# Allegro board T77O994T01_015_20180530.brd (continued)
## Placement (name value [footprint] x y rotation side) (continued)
R142  10Kohm  [C-0402B-U58O293T00]  113.33 42.16 90 bottom
R143  10Kohm  [R-0402S0]  116.99 33.4 90 bottom
R144  5.11Kohm  [R-0402S0]  111.31 53.2 90 bottom
R145  5.11Kohm  [R-0402S0]  110.77 51.05 180 bottom
R146  150ohm  [C-0402B-U58O293T00]  117.19 60.47 90 bottom
R147  5.11Kohm  [R-0402S0]  109.75 51.05 180 bottom
R148  10Kohm  [R-0402S0]  108.73 51.07 0 bottom
R149  75ohm  [C-0402B-U58O293T00]  118.91 57.91 90 bottom
R150  4.7Kohm  [R-0402S0]  94.28 18.92 180 top
R151  22ohm  [R-0402S0]  83.91 20.73 90 top
R152  22ohm  [R-0402S0]  83.86 18.16 90 top
R153  22ohm  [R-0402S0]  83.99 17.14 90 top
R154  1Kohm  [R-0402S0]  132.56 13.37 180 bottom
R155  1Kohm  [R-0402S0]  21.3 68.23 90 top
R156  1Kohm  [R-0402S0]  137.13 13.37 0 bottom
R157  10Kohm  [R-0402S0]  134.08 13.37 180 bottom
R158  10Kohm  [R-0402S0]  129.51 13.37 0 top
R159  10Kohm  [R-0402S0]  134.08 17.18 0 top
R160  7.5Kohm  [C-0402B-U58O293T00]  116.54 40.22 90 bottom
R161  10Kohm  [R-0402S0]  132.56 13.37 0 top
R162  10Kohm  [R-0402S0]  131.03 17.18 0 top
R163  10Kohm  [R-0402S0]  132.56 17.18 0 top
R164  10Kohm  [R-0402S0]  131.03 13.37 0 top
R165  10Kohm  [R-0402S0]  129.51 17.18 0 top
R166  5.11Kohm  [R-0402S0]  120.79 69.87 0 top
R167  8.2Kohm  [R-0402S0]  114.19 32 0 bottom
R168  10Kohm  [R-0402S0]  107.97 68.34 0 top
R169  49.9ohm  [C-0402B-U58O293T00]  116.33 56.59 180 bottom
R170  49.9ohm  [R-0402S0]  150.82 63.6 90 top
R171  49.9ohm  [R-0402S0]  150.82 62.63 90 top
R172  121ohm  [R-0402S0]  145.72 68.45 180 top
R173  40.2ohm  [R-0402S0]  144.7 68.45 180 top
R174  51ohm  [R-0402S0]  110.58 69.88 180 top
R175  51ohm  [R-0402S0]  116.2 64.3 90 bottom
R176  130ohm  [R-0402S0]  143.68 68.45 180 top
R177  10Kohm  [R-0402S0]  67.16 43.55 0 top
R178  51ohm  [R-0402S0]  112.62 69.88 0 top
R179  51ohm  [R-0402S0]  114.7 63.49 0 bottom
R180  10Kohm  [C-0402B-U58O293T00]  118.43 61.84 135 bottom
R181  10Kohm  [C-0402B-U58O293T00]  116.6 63.01 0 bottom
R182  7.5Kohm  [C-0402B-U58O293T00]  118.14 40.85 270 bottom
R183  33ohm  [R-0402S0]  184.28 3.06 270 top
R184  10Kohm  [C-0402B-U58O293T00]  127.6 34.29 180 bottom
R185  1Kohm  [R-0402S0]  135.6 13.37 180 top
R186  20ohm  [R-0402S0]  132.56 17.18 180 bottom
R187  20ohm  [R-0402S0]  138.65 13.37 0 top
R188  20ohm  [R-0402S0]  137.13 13.37 0 top
R189  1Kohm  [R-0402S0]  163.27 59.73 0 top
R190  2ohm  [R-0402S0]  153.65 65.55 270 top
R191  1Kohm  [R-0402S0]  163.27 61.38 0 top
R192  33ohm  [R-0402S0]  183.77 4.97 270 top
R193  150ohm  [R-0402S0]  63.86 28.59 0 top
R194  75ohm  [R-0402S0]  65 28.59 0 top
R195  75ohm  [R-0402S0]  66.14 28.59 0 top
R196  75ohm  [R-0402S0]  67.41 28.59 0 top
R197  49.9ohm  [R-0402S0]  38.23 67.58 270 bottom
R198  240ohm  [R-0402S0]  31.11 72.91 0 bottom
R199  10ohm  [R-0402S0]  32.26 72.91 180 bottom
R200  10Kohm  [R-0402S0]  83.34 28.69 90 top
R201  10Kohm  [R-0402S0]  83.34 30.98 90 top
R202  1Kohm  [R-0402S0]  83.34 29.83 90 top
R203  10Kohm  [R-0402S0]  27.24 67.96 90 top
R204  10Kohm  [R-0402S0]  36.93 28.08 0 top
R205  1Kohm  [R-0402S0]  111.71 72.43 0 top
R206  0ohm  [R-0402S0]  36.93 29.86 0 top
R207  10Kohm  [R-0402S0]  94.59 70.25 180 top
R208  33ohm  [R-0402S0]  87.1 70.37 270 top
R209  33ohm  [R-0402S0]  93.24 69.84 270 top
R210  10Kohm  [R-0402S0]  62.23 44.59 270 top
R211  0ohm  [R-0402S0]  62.33 45.86 90 top
R212  10Kohm  [R-0402S0]  37.48 44.69 180 top
R213  49.9ohm  [R-0402S0]  67.69 40.02 90 top
R214  4.7Kohm  [R-0402S0]  187.83 10.3 270 bottom
R215  33ohm  [R-0402S0]  171 4.05 90 bottom
R216  33ohm  [R-0402S0]  171 5.07 90 bottom
R217  33ohm  [R-0402S0]  171 7.1 90 bottom
R218  33ohm  [R-0402S0]  182.88 7.51 180 bottom
R219  0ohm  [R-0402S0]  66.29 12.34 180 top
R220  0ohm  [R-0402S0]  67.31 12.34 180 top
R221  33ohm  [R-0402S0]  183.77 7.76 270 top
R222  1Kohm  [R-0402S0]  168.02 2.84 90 top
R223  0ohm  [R-0402S0]  167.39 11.07 90 bottom
R224  330ohm  [R-0402S0]  187.83 11.32 90 bottom
R225  4.7Kohm  [R-0402S0]  167.36 7.74 90 top
R226  330ohm  [R-0402S0]  167.36 6.72 270 top
R227  4.7Kohm  [R-0402S0]  155.54 5.62 180 bottom
R228  4.7Kohm  [R-0402S0]  167.36 4.41 90 top
R229  0ohm  [R-0402S0]  189.71 79.77 270 bottom
R230  0ohm  [R-0402S0]  189.59 84.72 270 bottom
R231  0ohm  [R-0402S0]  188.56 61.48 90 top
R232  0ohm  [R-0402S0]  189.71 80.79 90 bottom
R233  0ohm  [R-0402S0]  189.59 85.74 90 bottom
R234  0ohm  [R-0402S0]  188.56 60.47 270 top
R235  0ohm  [R-0402S0]  160.76 82.69 270 top
R236  0ohm  [R-0402S0]  160.76 81.8 270 top
R237  0ohm  [R-0402S0]  160.73 83.6 270 top
R238  0ohm  [R-0402S0]  163.04 84.09 90 top
R239  0ohm  [R-0402S0]  163.04 82.31 90 top
R240  10Kohm  [R-0402S0]  129.51 8.03 180 bottom
R241  10Kohm  [R-0402S0]  138.65 17.18 180 bottom
R242  1Kohm  [R-0402S0]  119.73 18.07 180 bottom
R243  10Kohm  [R-0402S0]  135.6 8.03 180 bottom
R244  1Kohm  [R-0402S0]  129.51 8.03 180 top
R245  1Kohm  [R-0402S0]  138.65 17.18 180 top
R246  10Kohm  [R-0402S0]  119.73 18.07 180 top
R247  1Kohm  [R-0402S0]  135.6 8.03 180 top
R248  1Kohm  [R-0402S0]  137.13 17.18 180 bottom
R249  1Kohm  [R-0402S0]  135.6 17.18 180 bottom
R250  10Kohm  [R-0402S0]  129.51 17.18 180 bottom
R251  5.11Kohm  [R-0402S0]  117.75 69.87 180 top
R252  5.11Kohm  [R-0402S0]  113.25 74.46 180 top
R253  10Kohm  [R-0402S0]  137.13 17.18 0 top
R254  10Kohm  [R-0402S0]  135.6 17.18 180 top
R255  1Kohm  [R-0402S0]  129.51 13.37 0 bottom
R256  5.11Kohm  [R-0402S0]  117.75 72.15 0 top
R257  5.11Kohm  [R-0402S0]  110.7 72.43 0 top
R258  5.11Kohm  [R-0402S0]  100.6 60.21 90 bottom
R259  5.11Kohm  [R-0402S0]  116.73 69.87 180 top
R260  5.11Kohm  [R-0402S0]  119.78 69.87 180 top
R261  5.11Kohm  [C-0402B-U58O293T00]  120.21 57.47 180 bottom
R262  5.11Kohm  [C-0402B-U58O293T00]  121.33 57.47 180 bottom
R263  5.11Kohm  [R-0402S0]  100.6 60.21 90 top
R264  5.11Kohm  [R-0402S0]  116.73 72.15 0 top
R265  5.11Kohm  [R-0402S0]  120.65 72.15 0 top
R266  5.11Kohm  [C-0402B-U58O293T00]  120.41 59.31 180 bottom
R267  5.11Kohm  [C-0402B-U58O293T00]  122.6 57.4 90 bottom
R268  5.11Kohm  [C-0402B-U58O293T00]  120.06 63.32 90 bottom
R269  5.11Kohm  [R-0402S0]  119.71 69.89 0 bottom
R270  5.11Kohm  [R-0402S0]  115.71 69.87 180 top
R271  5.11Kohm  [R-0402S0]  121.89 27.08 0 bottom
R272  5.11Kohm  [R-0402S0]  100.6 63.26 90 top
R273  330Kohm  [R-0402S0]  122.9 27.08 0 bottom
R274  5.11Kohm  [C-0402B-U58O293T00]  121.22 62.45 90 bottom
R275  5.11Kohm  [R-0402S0]  118.82 69.89 180 bottom
R276  5.11Kohm  [R-0402S0]  115.71 72.15 0 top
R277  5.11Kohm  [R-0402S0]  98.95 63.26 90 top
R278  5.11Kohm  [R-0402S0]  112.92 63.49 90 bottom
R279  5.11Kohm  [R-0402S0]  100.6 61.23 90 bottom
R280  240ohm  [R-0402S0]  114.82 72.15 0 top
R281  240ohm  [R-0402S0]  114.82 74.44 180 top
R282  240ohm  [C-0402B-U58O293T00]  125.11 62.58 90 bottom
R283  5.11Kohm  [R-0402S0]  112.92 62.61 270 bottom
R284  5.11Kohm  [R-0402S0]  100.6 61.23 90 top
R285  240ohm  [R-0402S0]  114.78 72.17 0 bottom
R286  240ohm  [R-0402S0]  115.71 74.44 0 top
R287  240ohm  [R-0402S0]  124.76 56.71 180 bottom
R288  5.11Kohm  [R-0402S0]  93.22 70.83 90 top
R289  10Kohm  [R-0402S0]  138.65 8.03 0 top
R290  5.11Kohm  [R-0402S0]  100.6 62.12 90 top
R291  240ohm  [C-0402B-U58O293T00]  118.39 59.48 45 bottom
R292  240ohm  [R-0402S0]  123.87 56.72 0 bottom
R293  5.11Kohm  [R-0402S0]  93.98 72.79 90 top
R294  1Kohm  [R-0402S0]  138.65 8.03 0 bottom
R295  5.11Kohm  [R-0402S0]  98.95 62.12 90 top
R296  1Kohm  [R-0402S0]  134.08 8.03 180 bottom
R297  10Kohm  [R-0402S0]  140.18 13.37 180 bottom
R298  1Kohm  [R-0402S0]  135.6 3.72 180 bottom
R299  10Kohm  [R-0402S0]  126.46 13.37 180 bottom
R300  1Kohm  [R-0402S0]  134.08 8.03 180 top
R301  1Kohm  [R-0402S0]  140.18 13.37 180 top
R302  10Kohm  [R-0402S0]  135.6 3.72 180 top
R303  1Kohm  [R-0402S0]  126.46 17.18 0 bottom
R304  4.7Kohm  [R-0402S0]  155.54 3.84 0 bottom
R305  0ohm  [R-0402S0]  183.77 9.54 270 top
R306  10Kohm  [R-0402S0]  33.27 18.69 0 bottom
R307  10Kohm  [R-0402S0]  34.29 18.69 0 bottom
R308  0ohm  [R-0402S0]  22.99 20.84 0 bottom
R309  0ohm  [R-0603S0]  84.07 18.81 180 bottom
R310  0ohm  [R-0402S0]  186.31 11.07 180 top
R311  0ohm  [R-0402S0]  119.18 72.71 90 top
R312  0ohm  [R-0402S0]  196.09 12.69 270 top
R313  10Kohm  [R-0402S0]  36.45 18.69 0 bottom
R314  0ohm  [R-0402S0]  194.44 13.1 180 top
R315  4.7Kohm  [R-0402S0]  33.5 47.15 90 top
R316  4.7Kohm  [R-0402S0]  194.51 7.76 90 bottom
R317  0ohm  [R-0402S0]  28.54 53.5 180 top
R318  0ohm  [R-0402S0]  27.53 53.5 180 top
R319  330ohm  [R-0402S0]  28.8 47.02 180 top
R320  330ohm  [R-0402S0]  35.27 50.96 0 top
R321  330ohm  [R-0402S0]  35.28 49.29 0 top
R322  4.7Kohm  [R-0402S0]  70.48 70.5 0 top
R323  0ohm  [R-0402S0]  63.35 76.85 270 top
R324  0ohm  [R-0402S0]  63.35 78.12 270 top
R325  0ohm  [R-0402S0]  47.44 55.64 0 top
R326  4.7Kohm  [R-0402S0]  50.89 55.28 270 top
R327  4.7Kohm  [R-0402S0]  50.83 56.28 270 top
R328  0ohm  [R-0402S0]  41.16 61.14 90 bottom
R329  0ohm  [R-0402S0]  41.12 62.14 90 bottom
R330  0ohm  [R-0402S0]  50.86 57.42 90 top
R331  4.7Kohm  [R-0402S0]  53.48 59.87 270 bottom
R332  4.7Kohm  [R-0402S0]  48.61 61.32 90 top
R333  4.7Kohm  [R-0402S0]  50.69 61.99 270 top
R334  4.7Kohm  [R-0402S0]  53.43 61.88 270 bottom
R335  4.7Kohm  [R-0402S0]  42.82 59.11 90 bottom
R336  4.7Kohm  [R-0402S0]  53.43 62.9 90 bottom
R337  4.7Kohm  [R-0402S0]  42.82 60.13 270 bottom
R338  10Kohm  [R-0402S0]  31.73 23.89 0 bottom
R339  10Kohm  [R-0402S0]  44.32 24.02 0 bottom
R340  10Kohm  [R-0402S0]  41.61 24.35 270 bottom
R341  4.7Kohm  [R-0402S0]  75.91 38.64 0 bottom
R342  10Kohm  [R-0402S0]  41.62 23.27 90 bottom
R343  1Kohm  [R-0402S0]  76.55 40.42 0 bottom
R344  0ohm  [R-0402S0]  37.31 48.29 270 top
R345  0ohm  [R-0402S0]  62.08 40.91 90 top
R346  0ohm  [R-0402S0]  62.08 41.93 90 top
R347  0ohm  [R-0402S0]  62.59 48.4 90 top
R348  10Kohm  [R-0402S0]  66.67 18.94 0 bottom
R349  10Kohm  [R-0402S0]  67.82 18.94 0 bottom
R350  4.7Kohm  [R-0402S0]  194.51 6.75 270 bottom
R351  10Kohm  [R-0402S0]  183.36 10.94 180 top
R352  10Kohm  [R-0402S0]  185.29 11.07 0 top
R353  0ohm  [R-0402S0]  49.76 53.1 0 top
R354  0ohm  [R-0402S0]  50.78 53.1 0 top
R355  0ohm  [R-0402S0]  48.74 53.1 0 top
R356  0ohm  [R-0402S0]  47.73 53.1 0 top
R357  0ohm  [R-0402S0]  46.71 53.1 0 top
R358  0ohm  [R-0402S0]  44.68 53.1 0 top
R359  2.2ohm  [R-0402S0]  194.18 13.48 0 bottom
R360  10Kohm  [R-0402S0]  37.31 49.29 270 top
R361  4.7Kohm  [R-0402S0]  35.66 38.37 90 top
R362  330ohm  [R-0402S0]  37.31 50.31 90 top
R363  33ohm  [R-0402S0]  35.66 39.39 270 top
R364  0ohm  [R-0402S0]  50.13 39.28 0 bottom
R365  0ohm  [R-0402S0]  48.66 41.28 270 bottom
R366  4.7Kohm  [R-0402S0]  26.8 18.56 90 bottom
R367  4.7Kohm  [R-0402S0]  28.19 21.73 0 bottom
R368  4.7Kohm  [R-0402S0]  20.57 12.84 0 top
R369  1Kohm  [R-0402S0]  19.56 12.84 180 top
R370  0ohm  [R-0402S0]  53.17 34.71 270 bottom
R371  0ohm  [R-0402S0]  37.31 38.37 90 top
R372  0ohm  [R-0402S0]  52.55 29.5 180 top
R373  0ohm  [R-0402S0]  54.05 38.39 90 bottom
R374  0ohm  [R-0402S0]  35.66 41.54 90 top
R375  0ohm  [R-0402S0]  59.9 34.96 0 bottom
R376  0ohm  [R-0402S0]  35.66 40.4 90 top
R377  0ohm  [R-0402S0]  43.39 33.18 0 bottom
R378  0ohm  [R-0402S0]  61.95 36.59 270 top
R379  0ohm  [R-0402S0]  56.87 29.48 180 top
R380  150ohm  [R-0402S0]  58.9 58.96 0 top
R381  150ohm  [R-0402S0]  57.5 58.96 0 top
R382  150ohm  [R-0402S0]  55.98 58.94 0 top
R383  150ohm  [R-0402S0]  54.99 58.94 0 top
R384  4.7Kohm  [R-0402S0]  42.77 57.67 90 top
R385  10Kohm  [R-0402S0]  42.77 56.66 90 top
R386  4.7Kohm  [R-0402S0]  36.32 57.55 270 top
R387  0ohm  [R-0402S0]  42.77 58.69 270 top
R388  10Kohm  [R-0402S0]  69.52 80.08 90 bottom
R389  0ohm  [R-0402S0]  69.56 65.69 90 bottom
R390  1Kohm  [R-0402S0]  53.31 74.46 90 bottom
R391  0ohm  [R-0402S0]  69.52 81.09 90 bottom
R392  2.2Kohm  [R-0402S0]  69.56 70.14 270 bottom
R393  2.2Kohm  [R-0402S0]  69.52 82.11 270 bottom
R394  2.2Kohm  [R-0402S0]  69.56 83.73 270 bottom
R395  4.7Kohm  [R-0402S0]  183.77 6.75 90 top
R396  10Kohm  [R-0402S0]  126.46 13.37 180 top
R397  1Kohm  [R-0402S0]  4.03 69.76 90 bottom
R398  1Kohm  [R-0402S0]  19.62 67.07 90 top
R399  0ohm  [R-0402S0]  11.65 70.52 180 bottom
R400  0ohm  [R-0402S0]  5.85 67.71 270 bottom
R401  150ohm  [R-0402S0]  19.63 63.4 90 top
R402  0ohm  [R-0402S0]  25.11 67.98 90 top
R403  51ohm  [R-0402S0]  5.85 70.88 90 bottom
R404  0ohm  [R-0402S0]  38.19 66.2 90 bottom
R405  1Kohm  [R-0402S0]  19.65 60.49 90 top
R406  1Kohm  [R-0402S0]  5.85 68.72 90 bottom
R407  0ohm  [R-0402S0]  21.3 67.2 90 top
R408  0ohm  [R-0402S0]  4.03 70.9 90 bottom
R409  0ohm  [R-0402S0]  19.62 68.21 90 top
R410  0ohm  [R-0402S0]  6.9 72.79 90 bottom
R411  0ohm  [R-0402S0]  24.13 67.1 90 top
R412  51ohm  [R-0402S0]  11.31 63.9 270 bottom
R413  51ohm  [R-0402S0]  11.31 64.91 270 bottom
R414  10Kohm  [R-0402S0]  11.31 65.93 270 bottom
R415  10Kohm  [R-0402S0]  11.31 66.94 270 bottom
R416  51ohm  [R-0402S0]  11.31 67.96 270 bottom
R417  51ohm  [R-0402S0]  11.31 68.98 270 bottom
R418  10Kohm  [R-0402S0]  11.31 62.88 270 bottom
R419  51ohm  [R-0402S0]  11.31 61.86 270 bottom
R420  953ohm  [R-0402S0]  4.54 71.92 90 bottom
R421  33ohm  [R-0402S0]  159.38 10.43 90 top
R422  33ohm  [R-0402S0]  161.04 10.43 90 top
R423  4.7Kohm  [R-0402S0]  60.71 45.99 90 bottom
R424  4.7Kohm  [R-0402S0]  60.71 47.01 90 bottom
R425  4.7Kohm  [R-0402S0]  58.29 42.43 90 bottom
R426  4.7Kohm  [R-0402S0]  58.29 43.32 90 bottom
R427  4.7Kohm  [R-0402S0]  50.29 47.13 270 bottom
R428  4.7Kohm  [R-0402S0]  50.29 46.12 270 bottom
R429  4.7Kohm  [R-0402S0]  54.86 40.53 0 bottom
R430  4.7Kohm  [R-0402S0]  53.98 40.53 0 bottom
R431  4.7Kohm  [R-0402S0]  41.78 44.21 0 bottom
R432  4.7Kohm  [R-0402S0]  42.8 44.21 0 bottom
R433  4.7Kohm  [R-0402S0]  45.97 40.15 0 bottom
R434  4.7Kohm  [R-0402S0]  44.96 40.15 0 bottom
R435  4.7Kohm  [R-0402S0]  42.93 40.53 0 bottom
R436  4.7Kohm  [R-0402S0]  43.94 40.53 0 bottom
R437  10Kohm  [R-0402S0]  43.66 53.1 0 top
R438  10Kohm  [R-0402S0]  45.7 53.1 0 top
R439  10Kohm  [R-0402S0]  138.65 3.72 0 top
R440  10Kohm  [R-0402S0]  129.51 3.72 0 top
R441  10Kohm  [R-0402S0]  131.03 8.03 0 top
R442  10Kohm  [R-0402S0]  137.13 8.03 0 top
R443  33ohm  [R-0402S0]  167.39 5.45 90 top
R444  4.7Kohm  [R-0402S0]  37.34 52.21 90 top
R445  4.7Kohm  [R-0402S0]  35.31 47.64 0 top
R446  330ohm  [R-0402S0]  30.73 47.26 180 top
R447  0ohm  [R-0402S0]  25.65 20.59 90 bottom
R448  49.9ohm  [R-0402S0]  135.6 13.37 180 bottom
R449  0ohm  [R-0402S0]  163.04 85.11 90 top
R450  10Kohm  [R-0402S0]  48.78 55.01 180 top
R451  33ohm  [R-0402S0]  93.55 26.07 90 bottom
R452  33ohm  [R-0402S0]  93.55 27.09 90 bottom
R453  10ohm  [R-0402S0]  83.19 28.59 270 bottom
R454  10ohm  [R-0402S0]  83.19 29.61 270 bottom
R455  10ohm  [R-0402S0]  83.19 30.62 270 bottom
R456  10ohm  [R-0402S0]  83.19 31.64 270 bottom
R457  20ohm  [R-0402S0]  72.52 29.35 270 bottom
R458  20ohm  [R-0402S0]  76.2 24.78 0 bottom
R459  0ohm  [R-0402S0]  42.8 59.71 270 top
R460  1Kohm  [R-0402S0]  55.12 24.65 270 bottom
R461  0ohm  [R-0402S0]  58.04 21.23 90 bottom
R462  0ohm  [R-0402S0]  134.62 21.73 180 bottom
R463  0ohm  [R-0402S0]  127.34 23.98 180 bottom
R464  0ohm  [R-0402S0]  134.08 13.37 180 top
R465  0ohm  [R-0402S0]  77.85 41.55 270 bottom
R466  0ohm  [R-0402S0]  21.95 12.84 0 top
R467  0ohm  [R-0402S0]  23.09 12.84 0 top
R468  10Kohm  [R-0402S0]  108.33 74.69 0 top
R469  10Kohm  [R-0402S0]  109.35 74.69 0 top
TP1  TP  [ICT020]  126.39 28.7 180 bottom
TP3  TP  [ICT020]  129.68 25.67 180 bottom
TP4  TP  [ICT]  192.15 5.99 0 bottom
TP5  TP  [ICT020]  133.49 24.4 180 bottom
TP6  TP  [ICT020]  131.67 22.64 180 bottom
TP7  TP  [ICT020]  129.68 23.13 180 bottom
TP8  TP  [ICT020]  133.49 26.94 180 bottom
TP9  TP  [ICT020]  38.1 57.29 180 bottom
TP10  TP  [ICT020]  55.21 67.34 180 bottom
TP11  TP  [ICT020]  11.91 75.85 270 bottom
TP12  TP  [ICT020]  70.23 49.42 0 top
U1  BDX_DE  [EBGA-78X78-1667-U58O259T00]  126.01 46.27 0 top
U2  74AVCH1T45GW  [SOT-363S0]  83.16 64.66 180 top
U3  W25Q32JVSSIQ  [SO-8G]  75.58 65.4 0 bottom
U4  74AVCH4T245PW  [SSOP-16C]  75.06 65.7 180 top
U5  TXB0302DQMR  [ULGA-1_8X1_2-8]  90.32 26.48 180 bottom
U7  PCA9617ADP  [MSOP-8]  141.24 85.87 270 top
U8  74AVCH4T245PW  [SSOP-16C]  77.8 29.17 180 bottom
U9  CY2304NZZXC-1T  [MSOP-8A]  89.2 18.79 0 top
U10  74AVCH4T245PW  [SSOP-16C]  66.51 33.89 90 top
U11  74AVCH4T245PW  [SSOP-16C]  32.74 67.45 180 bottom
U12  74LVC1G07SE-7  [SC-70-5A]  72.16 28.44 90 top
U13  74AVCH4T245PW  [SSOP-16C]  77.8 29.19 180 top
U14  74AVCH4T245PW  [SSOP-16C]  32.78 67.44 180 top
U15  74AVCH4T245PW  [SSOP-16C]  31.83 29.85 180 top
U16  74AVCH1T45GW  [SOT-363S0]  89.89 70.88 180 top
U17  74LVC1G07SE-7  [SC-70-5A]  64.87 43.96 0 top
U18  74LVC1G07SE-7  [SC-70-5A]  35.21 45.12 0 top
U19  74LVC1G07SE-7  [SC-70-5A]  64.87 40.91 180 top
U20  SN74CB3Q3244PWR  [SSOP-20]  177.04 6.49 180 bottom
U21  NC7SB3157P6X  [UM-6BH1_1]  184.51 10.96 180 bottom
U22  NC7SB3157P6X  [UM-6BH1_1]  170.13 10 0 bottom
U23  MX25L12835FM2I-10G  [SO-8G]  161.29 6.13 0 top
U24  MX25L12835FM2I-10G  [SO-8G]  161.29 6.24 180 bottom
U25  SLB 9670XQ2.0 FW7.63  [TQFN-5X5-32NSH]  188.72 6.11 90 top
U26  M24128-BRDW6TP  [MSOP-8A]  30.32 50.22 0 top
U27  TMP75AIDR  [SO-8H1_75]  66.01 71.53 180 top
U28  74LVC1G07SE-7  [SC-70-5A]  48.24 59.07 90 top
U29  74LVC1G07SE-7  [SC-70-5A]  51.11 59.71 90 top
U30  PCA9539PW  [SSOP-24C]  48.15 58.6 0 bottom
U31  EPM1270F256I5N  [PBGA-16X16-256B-H2_2]  50.14 41.29 180 top
U32  74AVCH1T45GW  [SOT-363S0]  197.61 13.22 180 bottom
U33  74LVC1G08GW  [SOT-353-H1_1S0]  55.09 26.45 270 top
U34  TPS3808G33DBVR  [SOT-23-6]  39.55 57.61 0 top
U35  74AVCH2T45DC  [TSSOP-8S2]  45.47 27.96 90 top
U36  TMP235A2DCKR  [SC-70-5A]  110.87 44.72 270 bottom
Y1  25MHz  [O-S3_2X2_5-4F]  101.37 56.64 0 top
Y2  32.768KHz  [O-3_2X1_5-2A]  122.81 18.81 90 top
Y3  25MHz  [O-3_2X2_5-4GS0]  112.04 18.03 90 top
Y4  25MHz  [O-3_2X2_5-4JS0]  31.98 38.24 0 top

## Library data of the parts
BAT1 = BB3320E
C1-C8 = CAP: signal model: CAP_C-0402S0_220NF_220nF
C9-C16 = CAP: signal model: CAP_C-0402S0_100NF_100nF
C17-C104 C107 C108 C114 C116-C141 C144-C148 C151-C183 C185-C193 C198-C200 C205-C210 C3812 C3813 PC2-PC5 PC7 PC11-PC15 PC18-PC21 PC24-PC41 PC44-PC48 PC52 PC67 PC68 PC70-PC72 PC75 PC77-PC84 PC111-PC115 PC137 PC139 PC140 PC142 PC144 PC146-PC148 PC151 PC162 PC163 PC165-PC168 PC170-PC172 PC174-PC178 PC180 PC182-PC184 PC186-PC196 PC199-PC206 PC208 PC209 PC211-PC220 PC222-PC231 PC233-PC236 PC238-PC241 PC243 PC244 PC246-PC250 PC252 PC255 PC262 PC264-PC267 PC270-PC275 PC295-PC307 PC309 PC312 PC313 PC316 PC318 PC322 PC325-PC336 PC338-PC340 PC347-PC349 = CAP
C201-C204 = CAP: signal model: CAP_C-0402S0_10NF_10nF
CN1 CN2 = DDR4 ECC SODIMM CONN_2
D1 D3-D6 = LED
D2 D7 D8 = BAT54CLT1
H1 MHS1-MHS4 = TOOLING HOLE-1PIN-MPTH
J1 = CON7X2
J2 = CON4X1
J3 = CON4X1_0
J6 = CON4X2
J8 = CON5X2
J9 = AS0BC23-S67BM-LH_0
J10 = PCIE CONN_0
J11 = CON2X2
J12 = CON30X2
L1 PJ20-PJ22 PR7-PR26 PR31-PR38 PR42 PR57 PR73 PR79 PR80 PR107-PR112 PR114-PR207 PR209 PR210 PR217 PR235 PR242-PR252 PR254 PR259-PR261 PR263 PR265-PR269 PR271-PR282 PR284-PR287 PR289-PR305 R1-R21 R29-R469 = RES
L2 L3 L7 PL1 PL2 PL8-PL16 = INDUCTOR
M1-M4 = Hole-MTG-8VIA
PC1 PC6 PC16 PC17 PC258 PC259 = CAP_0
PC8-PC10 PC22 PC23 PC69 PC257 PC263 = CAP_0: signal model: DEFAULT_CAPACITOR_2.2e+07pF_1_2
PC152 PC173 PC179 PC185 PC232 PC237 PC242 PC256 PC284 PC292 PC293 PC323 PC324 = CAP AL
PNTC2-PNTC8 = THERMISTOR
PR1 PR2 PR222 PR223 PR226 PR228 PR231 PR233 PR237 PR239 = RES_0
PR214-PR216 PR218 PR219 PR221 PR224 PR227 PR229 PR232 PR234 PR236 PR238 PR241 = RES_11
PU1 PU20 = TPS562219_563219
PU2 = TPS56628DDAR
PU5 PU6 = TPS74801DRCR
PU11 = TPS51200
PU14 = TPS54618RTER
PU17 = P_TPS51620RHAR_QFN40_1: room: PWR_VCORE
PU18 PU19 PU22 PU26 = CSD95373AQ5M
PU21 PU27 = TPS53623RSMR
PU24 = NCP45540IMNTWG-H
PU25 = NCP45520IMNTWG
Q1 Q4 Q5 = NFETX2-6P-SGD
Q2 Q3 Q6 = NPN-3P-BEC
TP1 TP3-TP12 = TP
U1 = BDX_DE_NEW
U2 U16 U32 = 74AVCH1T45GW
U3 = W25X40AVSNIG
U4 U8 U10 U11 U13-U15 = 74AVCH4T245PW
U5 = TXS0102DQER
U7 = PCA9617ADPJ
U9 = CY2304NZ
U12 U17-U19 U28 U29 = 74LVC1G34GW
U20 = QS3VH244PAG_0
U21 U22 = NC7SB3157P6X
U23 U24 = MX25L12835FM2I-10G
U25 = SLB 9670VQ2_4
U26 = AT24C02N
U27 = TMP75AIDR
U30 = PCA9539PW
U31 = EPM1270F256C5
U33 = 74LVC1G08
U34 = TPS3808G33DBVR
U35 = SN74AVC2T45DCUR_0
U36 = TPS71701DCKR_1
Y1 Y3 = XTAL-4
Y2 = XTAL
Y4 = OSC4PIN

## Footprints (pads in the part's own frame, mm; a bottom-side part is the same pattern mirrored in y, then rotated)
BA-D23_1X5_8-3S0
  round 1.575 hole 0.965: P1(5,-1.8) P3(-5,-1.8)
  round 1.549 hole 0.94: P2(0,1.8)
C-0402A
  custom 0.153x0.153 smd: 1(0,-0.459) 2(0,0.459)
C-0402B-U58O293T00
  custom 0.104x0.104 smd: 1(0,-0.4) 2(0,0.4)
C-0402S0
  custom 0.127x0.127 smd: 1(0,-0.406) 2(0,0.406)
C-0603S0
  custom 0.191x0.191 smd: 1(0,-0.686) 2(0,0.686)
C-0805
  custom 0.254x0.254 smd: 1(0,-0.889) 2(0,0.889)
C-0805-H1_35
  custom 0.254x0.254 smd: 1(0,-0.889) 2(0,0.889)
C-1206
  custom 0.362x0.362 smd: 1(0,-1.333) 2(0,1.333)
C-1210
  custom 0.381x0.381 smd: 1(0,-1.27) 2(0,1.27)
C-1210B-H2_8
  custom 0.381x0.381 smd: 1(0,-1.27) 2(0,1.27)
C-S7_3X4_3-2
  rect 2.896x2.083 smd: 1(0,-3.117) 2(0,3.117)
C-TAN-S7_3X4_3
  rect 2.997x2.007 smd: 1(0,3.003) 2(0,-3.003)
CN-D2X2-4_2RT
  round 2.997 hole 2.997 unplated: (0,-0.2)
  round 2.311 hole 1.702: 1(-2.1,-7.5) 2(2.1,-7.5) 3(-2.1,-13) 4(2.1,-13)
CN-EXPPCI-75G
  round 1.295 hole 1.295 unplated: (1.375,-10)
  round 1.753 hole 1.753 unplated: (1.375,10)
  rect 1.27x0.305 smd: 1(-4.348,-9.253) 3(-4.348,-8.753) 5(-4.348,-8.253) 7(-4.348,-7.753) 9(-4.348,-7.253) 11(-4.348,-6.753) 13(-4.348,-6.253) 15(-4.348,-5.753) 17(-4.348,-5.252) 19(-4.348,-4.752) 21(-4.348,-4.252) 23(-4.348,-3.752) 25(-4.348,-3.252) 27(-4.348,-2.752) 29(-4.348,-2.252) 31(-4.348,-1.752) 33(-4.348,-1.251) 35(-4.348,-0.751) 37(-4.348,-0.251) 39(-4.348,0.249) 41(-4.348,0.749) 43(-4.348,1.249) 45(-4.348,1.749) 47(-4.348,2.249) 49(-4.348,2.75) 51(-4.348,3.25) 53(-4.348,3.75) 55(-4.348,4.25) 57(-4.348,4.75) 67(-4.348,7.25) 69(-4.348,7.75) 71(-4.348,8.25) 73(-4.348,8.751) 75(-4.348,9.251)
  rect 1.219x0.305 smd: 2(4.123,-9.004) 4(4.123,-8.503) 6(4.123,-8.003) 8(4.123,-7.503) 10(4.123,-7.003) 12(4.123,-6.503) 14(4.123,-6.003) 16(4.123,-5.503) 18(4.123,-5.003) 20(4.123,-4.502) 22(4.123,-4.002) 24(4.123,-3.502) 26(4.123,-3.002) 28(4.123,-2.502) 30(4.123,-2.002) 32(4.123,-1.502) 34(4.123,-1.002) 36(4.123,-0.501) 38(4.123,-0.001) 40(4.123,0.499) 42(4.123,0.999) 44(4.123,1.499) 46(4.123,1.999) 48(4.123,2.499) 50(4.123,2.999) 52(4.123,3.5) 54(4.123,4) 56(4.123,4.5) 58(4.123,5) 68(4.123,7.5) 70(4.123,8) 72(4.123,8.5) 74(4.123,9)
  rect 3.15x1.575 smd: S1(-3.125,10.35) S2(-3.125,-10.35)
CN-EXPPCI-164FPCS0
  rect 3.2x0.711 smd: A1(-2.38,-41.5) B81(-2.38,40.5)
  rect 4.191x0.711 smd: A2(-2.875,-40.5) A3(-2.875,-39.5) A4(-2.875,-38.5) A5(-2.875,-37.5) A6(-2.875,-36.5) A7(-2.875,-35.5) A8(-2.875,-34.5) A9(-2.875,-33.5) A10(-2.875,-32.5) A11(-2.875,-31.5) A12(-2.875,-28.5) A13(-2.875,-27.5) A14(-2.875,-26.5) A15(-2.875,-25.5) A16(-2.875,-24.5) A17(-2.875,-23.5) A18(-2.875,-22.5) A19(-2.875,-21.5) A20(-2.875,-20.5) A21(-2.875,-19.5) A22(-2.875,-18.5) A23(-2.875,-17.5) A24(-2.875,-16.5) A25(-2.875,-15.5) A26(-2.875,-14.5) A27(-2.875,-13.5) A28(-2.875,-12.5) A29(-2.875,-11.5) A30(-2.875,-10.5) A31(-2.875,-9.5) A32(-2.875,-8.5) A33(-2.875,-7.5) A34(-2.875,-6.5) A35(-2.875,-5.5) A36(-2.875,-4.5) A37(-2.875,-3.5) A38(-2.875,-2.5) A39(-2.875,-1.5) A40(-2.875,-0.5) A41(-2.875,0.5) A42(-2.875,1.5) A43(-2.875,2.5) A44(-2.875,3.5) A45(-2.875,4.5) A46(-2.875,5.5) A47(-2.875,6.5) A48(-2.875,7.5) A49(-2.875,8.5) A50(-2.875,9.5) A51(-2.875,10.5) A52(-2.875,11.5) A53(-2.875,12.5) A54(-2.875,13.5) A55(-2.875,14.5) A56(-2.875,15.5) A57(-2.875,16.5) A58(-2.875,17.5) A59(-2.875,18.5) A60(-2.875,19.5) A61(-2.875,20.5) A62(-2.875,21.5) A63(-2.875,22.5) A64(-2.875,23.5) A65(-2.875,24.5) A66(-2.875,25.5) A67(-2.875,26.5) A68(-2.875,27.5) A69(-2.875,28.5) A70(-2.875,29.5) A71(-2.875,30.5) A72(-2.875,31.5) A73(-2.875,32.5) A74(-2.875,33.5) A75(-2.875,34.5) A76(-2.875,35.5) A77(-2.875,36.5) A78(-2.875,37.5) A79(-2.875,38.5) A80(-2.875,39.5) A81(-2.875,40.5) A82(-2.875,41.5) B1(-2.875,-41.5) B2(-2.875,-40.5) B3(-2.875,-39.5) B4(-2.875,-38.5) B5(-2.875,-37.5) B6(-2.875,-36.5) B7(-2.875,-35.5) B8(-2.875,-34.5) B9(-2.875,-33.5) B10(-2.875,-32.5) B11(-2.875,-31.5) B12(-2.875,-28.5) B13(-2.875,-27.5) B14(-2.875,-26.5) B15(-2.875,-25.5) B16(-2.875,-24.5) B17(-2.875,-23.5) B18(-2.875,-22.5) B19(-2.875,-21.5) B20(-2.875,-20.5) B21(-2.875,-19.5) B22(-2.875,-18.5) B23(-2.875,-17.5) B24(-2.875,-16.5) B25(-2.875,-15.5) B26(-2.875,-14.5) B27(-2.875,-13.5) B28(-2.875,-12.5) B29(-2.875,-11.5) B30(-2.875,-10.5) B31(-2.875,-9.5) B32(-2.875,-8.5) B33(-2.875,-7.5) B34(-2.875,-6.5) B35(-2.875,-5.5) B36(-2.875,-4.5) B37(-2.875,-3.5) B38(-2.875,-2.5) B39(-2.875,-1.5) B40(-2.875,-0.5) B41(-2.875,0.5) B42(-2.875,1.5) B43(-2.875,2.5) B44(-2.875,3.5) B45(-2.875,4.5) B46(-2.875,5.5) B47(-2.875,6.5) B48(-2.875,7.5) B49(-2.875,8.5) B50(-2.875,9.5) B51(-2.875,10.5) B52(-2.875,11.5) B53(-2.875,12.5) B54(-2.875,13.5) B55(-2.875,14.5) B56(-2.875,15.5) B57(-2.875,16.5) B58(-2.875,17.5) B59(-2.875,18.5) B60(-2.875,19.5) B61(-2.875,20.5) B62(-2.875,21.5) B63(-2.875,22.5) B64(-2.875,23.5) B65(-2.875,24.5) B66(-2.875,25.5) B67(-2.875,26.5) B68(-2.875,27.5) B69(-2.875,28.5) B70(-2.875,29.5) B71(-2.875,30.5) B72(-2.875,31.5) B73(-2.875,32.5) B74(-2.875,33.5) B75(-2.875,34.5) B76(-2.875,35.5) B77(-2.875,36.5) B78(-2.875,37.5) B79(-2.875,38.5) B80(-2.875,39.5) B82(-2.875,41.5)
CN-EXPPCI-260A-T77O759
  round 1.753 hole 1.753 unplated: (-34.4,0)
  round 1.194 hole 1.194 unplated: (34.4,0)
  rect 0.305x1.473 smd: 1(-33.383,-3.971) 2(-33.133,3.971) 3(-32.883,-3.971) 4(-32.633,3.971) 5(-32.383,-3.971) 6(-32.133,3.971) 7(-31.883,-3.971) 8(-31.633,3.971) 9(-31.383,-3.971) 10(-31.133,3.971) 11(-30.883,-3.971) 12(-30.633,3.971) 13(-30.383,-3.971) 14(-30.133,3.971) 15(-29.883,-3.971) 16(-29.632,3.971) 17(-29.382,-3.971) 18(-29.132,3.971) 19(-28.882,-3.971) 20(-28.632,3.971) 21(-28.382,-3.971) 22(-28.132,3.971) 23(-27.882,-3.971) 24(-27.632,3.971) 25(-27.382,-3.971) 26(-27.132,3.971) 27(-26.882,-3.971) 28(-26.632,3.971) 29(-26.382,-3.971) 30(-26.132,3.971) 31(-25.882,-3.971) 32(-25.631,3.971) 33(-25.381,-3.971) 34(-25.131,3.971) 35(-24.881,-3.971) 36(-24.631,3.971) 37(-24.381,-3.971) 38(-24.131,3.971) 39(-23.881,-3.971) 40(-23.631,3.971) 41(-23.381,-3.971) 42(-23.131,3.971) 43(-22.881,-3.971) 44(-22.631,3.971) 45(-22.381,-3.971) 46(-22.131,3.971) 47(-21.881,-3.971) 48(-21.63,3.971) 49(-21.38,-3.971) 50(-21.13,3.971) 51(-20.88,-3.971) 52(-20.63,3.971) 53(-20.38,-3.971) 54(-20.13,3.971) 55(-19.88,-3.971) 56(-19.63,3.971) 57(-19.38,-3.971) 58(-19.13,3.971) 59(-18.88,-3.971) 60(-18.63,3.971) 61(-18.38,-3.971) 62(-18.13,3.971) 63(-17.88,-3.971) 64(-17.629,3.971) 65(-17.379,-3.971) 66(-17.129,3.971) 67(-16.879,-3.971) 68(-16.629,3.971) 69(-16.379,-3.971) 70(-16.129,3.971) 71(-15.879,-3.971) 72(-15.629,3.971) 73(-15.379,-3.971) 74(-15.129,3.971) 75(-14.879,-3.971) 76(-14.629,3.971) 77(-14.379,-3.971) 78(-14.128,3.971) 79(-13.879,-3.971) 80(-13.628,3.971) 81(-13.378,-3.971) 82(-13.128,3.971) 83(-12.878,-3.971) 84(-12.628,3.971) 85(-12.378,-3.971) 86(-12.128,3.971) 87(-11.878,-3.971) 88(-11.628,3.971) 89(-11.378,-3.971) 90(-11.128,3.971) 91(-10.878,-3.971) 92(-10.628,3.971) 93(-10.378,-3.971) 94(-10.127,3.971) 95(-9.878,-3.971) 96(-9.627,3.971) 97(-9.377,-3.971) 98(-9.127,3.971) 99(-8.877,-3.971) 100(-8.627,3.971) 101(-8.377,-3.971) 102(-8.127,3.971) 103(-7.877,-3.971) 104(-7.627,3.971) 105(-7.377,-3.971) 106(-7.127,3.971) 107(-6.877,-3.971) 108(-6.627,3.971) 109(-6.377,-3.971) 110(-6.126,3.971) 111(-5.877,-3.971) 112(-5.626,3.971) 113(-5.376,-3.971) 114(-5.126,3.971) 115(-4.876,-3.971) 116(-4.626,3.971) 117(-4.376,-3.971) 118(-4.126,3.971) 119(-3.876,-3.971) 120(-3.626,3.971) 121(-3.376,-3.971) 122(-3.126,3.971) 123(-2.876,-3.971) 124(-2.626,3.971) 125(-2.376,-3.971) 126(-2.125,3.971) 127(-1.876,-3.971) 128(-1.625,3.971) 129(-1.375,-3.971) 130(-1.125,3.971) 131(-0.875,-3.971) 132(-0.625,3.971) 133(-0.375,-3.971) 134(-0.125,3.971) 135(0.125,-3.971) 136(0.375,3.971) 137(0.625,-3.971) 138(0.875,3.971) 139(1.125,-3.971) 140(1.375,3.971) 141(1.625,-3.971) 142(1.876,3.971) 143(2.125,-3.971) 144(2.376,3.971) 145(4.626,-3.971) 146(4.876,3.971) 147(5.126,-3.971) 148(5.376,3.971) 149(5.626,-3.971) 150(5.877,3.971) 151(6.126,-3.971) 152(6.377,3.971) 153(6.627,-3.971) 154(6.877,3.971) 155(7.127,-3.971) 156(7.377,3.971) 157(7.627,-3.971) 158(7.877,3.971) 159(8.127,-3.971) 160(8.377,3.971) 161(8.627,-3.971) 162(8.877,3.971) 163(9.127,-3.971) 164(9.377,3.971) 165(9.627,-3.971) 166(9.878,3.971) 167(10.127,-3.971) 168(10.378,3.971) 169(10.628,-3.971) 170(10.878,3.971) 171(11.128,-3.971) 172(11.378,3.971) 173(11.628,-3.971) 174(11.878,3.971) 175(12.128,-3.971) 176(12.378,3.971) 177(12.628,-3.971) 178(12.878,3.971) 179(13.128,-3.971) 180(13.378,3.971) 181(13.628,-3.971) 182(13.879,3.971) 183(14.128,-3.971) 184(14.379,3.971) 185(14.629,-3.971) 186(14.879,3.971) 187(15.129,-3.971) 188(15.379,3.971) 189(15.629,-3.971) 190(15.879,3.971) 191(16.129,-3.971) 192(16.379,3.971) 193(16.629,-3.971) 194(16.879,3.971) 195(17.129,-3.971) 196(17.379,3.971) 197(17.629,-3.971) 198(17.88,3.971) 199(18.13,-3.971) 200(18.38,3.971) 201(18.63,-3.971) 202(18.88,3.971) 203(19.13,-3.971) 204(19.38,3.971) 205(19.63,-3.971) 206(19.88,3.971) 207(20.13,-3.971) 208(20.38,3.971) 209(20.63,-3.971) 210(20.88,3.971) 211(21.13,-3.971) 212(21.38,3.971) 213(21.63,-3.971) 214(21.881,3.971) 215(22.131,-3.971) 216(22.381,3.971) 217(22.631,-3.971) 218(22.881,3.971) 219(23.131,-3.971) 220(23.381,3.971) 221(23.631,-3.971) 222(23.881,3.971) 223(24.131,-3.971) 224(24.381,3.971) 225(24.631,-3.971) 226(24.881,3.971) 227(25.131,-3.971) 228(25.381,3.971) 229(25.631,-3.971) 230(25.882,3.971) 231(26.132,-3.971) 232(26.382,3.971) 233(26.632,-3.971) 234(26.882,3.971) 235(27.132,-3.971) 236(27.382,3.971) 237(27.632,-3.971) 238(27.882,3.971) 239(28.132,-3.971) 240(28.382,3.971) 241(28.632,-3.971) 242(28.882,3.971) 243(29.132,-3.971) 244(29.382,3.971) 245(29.632,-3.971) 246(29.883,3.971) 247(30.133,-3.971) 248(30.383,3.971) 249(30.633,-3.971) 250(30.883,3.971) 251(31.133,-3.971) 252(31.383,3.971) 253(31.633,-3.971) 254(31.883,3.971) 255(32.133,-3.971) 256(32.383,3.971) 257(32.633,-3.971) 258(32.883,3.971) 259(33.133,-3.971) 260(33.383,3.971)
  rect 0.406x0.406 smd: S1(32.455,-11.874) S2(-32.455,-11.874)
CN-EXPPCI-260C
  round 1.753 hole 1.753 unplated: (-34.4,0)
  round 1.194 hole 1.194 unplated: (34.4,0)
  rect 0.305x1.473 smd: 1(-33.391,-3.871) 2(-33.141,3.871) 3(-32.891,-3.871) 4(-32.641,3.871) 5(-32.391,-3.871) 6(-32.141,3.871) 7(-31.891,-3.871) 8(-31.641,3.871) 9(-31.391,-3.871) 10(-31.141,3.871) 11(-30.891,-3.871) 12(-30.641,3.871) 13(-30.391,-3.871) 14(-30.14,3.871) 15(-29.89,-3.871) 16(-29.64,3.871) 17(-29.39,-3.871) 18(-29.14,3.871) 19(-28.89,-3.871) 20(-28.64,3.871) 21(-28.39,-3.871) 22(-28.14,3.871) 23(-27.89,-3.871) 24(-27.64,3.871) 25(-27.39,-3.871) 26(-27.14,3.871) 27(-26.89,-3.871) 28(-26.64,3.871) 29(-26.39,-3.871) 30(-26.139,3.871) 31(-25.889,-3.871) 32(-25.639,3.871) 33(-25.389,-3.871) 34(-25.139,3.871) 35(-24.889,-3.871) 36(-24.639,3.871) 37(-24.389,-3.871) 38(-24.139,3.871) 39(-23.889,-3.871) 40(-23.639,3.871) 41(-23.389,-3.871) 42(-23.139,3.871) 43(-22.889,-3.871) 44(-22.639,3.871) 45(-22.389,-3.871) 46(-22.138,3.871) 47(-21.888,-3.871) 48(-21.638,3.871) 49(-21.388,-3.871) 50(-21.138,3.871) 51(-20.888,-3.871) 52(-20.638,3.871) 53(-20.388,-3.871) 54(-20.138,3.871) 55(-19.888,-3.871) 56(-19.638,3.871) 57(-19.388,-3.871) 58(-19.138,3.871) 59(-18.888,-3.871) 60(-18.638,3.871) 61(-18.388,-3.871) 62(-18.137,3.871) 63(-17.887,-3.871) 64(-17.637,3.871) 65(-17.387,-3.871) 66(-17.137,3.871) 67(-16.887,-3.871) 68(-16.637,3.871) 69(-16.387,-3.871) 70(-16.137,3.871) 71(-15.887,-3.871) 72(-15.637,3.871) 73(-15.387,-3.871) 74(-15.137,3.871) 75(-14.887,-3.871) 76(-14.636,3.871) 77(-14.387,-3.871) 78(-14.136,3.871) 79(-13.886,-3.871) 80(-13.636,3.871) 81(-13.386,-3.871) 82(-13.136,3.871) 83(-12.886,-3.871) 84(-12.636,3.871) 85(-12.386,-3.871) 86(-12.136,3.871) 87(-11.886,-3.871) 88(-11.636,3.871) 89(-11.386,-3.871) 90(-11.136,3.871) 91(-10.886,-3.871) 92(-10.635,3.871) 93(-10.386,-3.871) 94(-10.135,3.871) 95(-9.885,-3.871) 96(-9.635,3.871) 97(-9.385,-3.871) 98(-9.135,3.871) 99(-8.885,-3.871) 100(-8.635,3.871) 101(-8.385,-3.871) 102(-8.135,3.871) 103(-7.885,-3.871) 104(-7.635,3.871) 105(-7.385,-3.871) 106(-7.135,3.871) 107(-6.885,-3.871) 108(-6.634,3.871) 109(-6.385,-3.871) 110(-6.134,3.871) 111(-5.884,-3.871) 112(-5.634,3.871) 113(-5.384,-3.871) 114(-5.134,3.871) 115(-4.884,-3.871) 116(-4.634,3.871) 117(-4.384,-3.871) 118(-4.134,3.871) 119(-3.884,-3.871) 120(-3.634,3.871) 121(-3.384,-3.871) 122(-3.134,3.871) 123(-2.884,-3.871) 124(-2.633,3.871) 125(-2.384,-3.871) 126(-2.133,3.871) 127(-1.883,-3.871) 128(-1.633,3.871) 129(-1.383,-3.871) 130(-1.133,3.871) 131(-0.883,-3.871) 132(-0.633,3.871) 133(-0.383,-3.871) 134(-0.133,3.871) 135(0.117,-3.871) 136(0.367,3.871) 137(0.617,-3.871) 138(0.867,3.871) 139(1.117,-3.871) 140(1.368,3.871) 141(1.617,-3.871) 142(1.868,3.871) 143(2.118,-3.871) 144(2.368,3.871) 145(4.618,-3.871) 146(4.868,3.871) 147(5.118,-3.871) 148(5.368,3.871) 149(5.618,-3.871) 150(5.868,3.871) 151(6.118,-3.871) 152(6.368,3.871) 153(6.618,-3.871) 154(6.868,3.871) 155(7.118,-3.871) 156(7.369,3.871) 157(7.618,-3.871) 158(7.869,3.871) 159(8.119,-3.871) 160(8.369,3.871) 161(8.619,-3.871) 162(8.869,3.871) 163(9.119,-3.871) 164(9.369,3.871) 165(9.619,-3.871) 166(9.869,3.871) 167(10.119,-3.871) 168(10.369,3.871) 169(10.619,-3.871) 170(10.869,3.871) 171(11.119,-3.871) 172(11.37,3.871) 173(11.619,-3.871) 174(11.87,3.871) 175(12.12,-3.871) 176(12.37,3.871) 177(12.62,-3.871) 178(12.87,3.871) 179(13.12,-3.871) 180(13.37,3.871) 181(13.62,-3.871) 182(13.87,3.871) 183(14.12,-3.871) 184(14.37,3.871) 185(14.62,-3.871) 186(14.87,3.871) 187(15.12,-3.871) 188(15.371,3.871) 189(15.62,-3.871) 190(15.871,3.871) 191(16.121,-3.871) 192(16.371,3.871) 193(16.621,-3.871) 194(16.871,3.871) 195(17.121,-3.871) 196(17.371,3.871) 197(17.621,-3.871) 198(17.871,3.871) 199(18.121,-3.871) 200(18.371,3.871) 201(18.621,-3.871) 202(18.871,3.871) 203(19.121,-3.871) 204(19.372,3.871) 205(19.622,-3.871) 206(19.872,3.871) 207(20.122,-3.871) 208(20.372,3.871) 209(20.622,-3.871) 210(20.872,3.871) 211(21.122,-3.871) 212(21.372,3.871) 213(21.622,-3.871) 214(21.872,3.871) 215(22.122,-3.871) 216(22.372,3.871) 217(22.622,-3.871) 218(22.872,3.871) 219(23.122,-3.871) 220(23.373,3.871) 221(23.623,-3.871) 222(23.873,3.871) 223(24.123,-3.871) 224(24.373,3.871) 225(24.623,-3.871) 226(24.873,3.871) 227(25.123,-3.871) 228(25.373,3.871) 229(25.623,-3.871) 230(25.873,3.871) 231(26.123,-3.871) 232(26.373,3.871) 233(26.623,-3.871) 234(26.873,3.871) 235(27.123,-3.871) 236(27.374,3.871) 237(27.624,-3.871) 238(27.874,3.871) 239(28.124,-3.871) 240(28.374,3.871) 241(28.624,-3.871) 242(28.874,3.871) 243(29.124,-3.871) 244(29.374,3.871) 245(29.624,-3.871) 246(29.874,3.871) 247(30.124,-3.871) 248(30.374,3.871) 249(30.624,-3.871) 250(30.874,3.871) 251(31.124,-3.871) 252(31.375,3.871) 253(31.625,-3.871) 254(31.875,3.871) 255(32.125,-3.871) 256(32.375,3.871) 257(32.625,-3.871) 258(32.875,3.871) 259(33.125,-3.871) 260(33.375,3.871)
  rect 2.413x3.912 smd: S1(-37.75,-8) S2(37.75,-12)
CN-S4X2-2_54HD
  rect 2.362x1.245 smd: 1(3.007,-3.81) 2(-3.007,-3.81) 3(3.007,-1.27) 4(-3.007,-1.27) 5(3.007,1.27) 6(-3.007,1.27) 7(3.007,3.81) 8(-3.007,3.81)
CN-S5X2-2_54AHDS0
  rect 2.362x1.245 smd: 1(3.007,-5.08) 2(-3.007,-5.08) 3(3.007,-2.54) 4(-3.007,-2.54) 5(3.007,0) 6(-3.007,0) 7(3.007,2.54) 8(-3.007,2.54) 9(3.007,5.08) 10(-3.007,5.08)
CN-S7X2-2HDS1
  round 1.143 hole 1.143 unplated: (0,5) (0,-5)
  rect 1.829x0.813 smd: 1(2.644,-6) 2(-2.644,-6) 3(2.644,-4) 4(-2.644,-4) 5(2.644,-2) 6(-2.644,-2) 7(2.644,0) 8(-2.644,0) 9(2.644,2) 10(-2.644,2) 11(2.644,4) 12(-2.644,4) 13(2.644,6) 14(-2.644,6)
CN-S10_16X5_1-4
  rect 3.099x0.965 smd: 1(1.562,3.81) 2(-1.562,1.27) 3(1.562,-1.27) 4(-1.562,-3.81)
CN-S30X2-0_5ASK
  round 1.194 hole 1.194 unplated: (2.67,10.065) (2.67,-10.065)
  rect 2.54x0.305 smd: 1(-2.985,7.252) 2(2.985,7.252) 3(-2.985,6.752) 4(2.985,6.752) 5(-2.985,6.251) 6(2.985,6.251) 7(-2.985,5.751) 8(2.985,5.751) 9(-2.985,5.251) 10(2.985,5.251) 11(-2.985,4.751) 12(2.985,4.751) 13(-2.985,4.251) 14(2.985,4.251) 15(-2.985,3.751) 16(2.985,3.751) 17(-2.985,3.251) 18(2.985,3.251) 19(-2.985,2.751) 20(2.985,2.751) 21(-2.985,2.25) 22(2.985,2.25) 23(-2.985,1.75) 24(2.985,1.75) 25(-2.985,1.25) 26(2.985,1.25) 27(-2.985,0.75) 28(2.985,0.75) 29(-2.985,0.25) 30(2.985,0.25) 31(-2.985,-0.25) 32(2.985,-0.25) 33(-2.985,-0.75) 34(2.985,-0.75) 35(-2.985,-1.25) 36(2.985,-1.25) 37(-2.985,-1.75) 38(2.985,-1.75) 39(-2.985,-2.25) 40(2.985,-2.25) 41(-2.985,-2.751) 42(2.985,-2.751) 43(-2.985,-3.251) 44(2.985,-3.251) 45(-2.985,-3.751) 46(2.985,-3.751) 47(-2.985,-4.251) 48(2.985,-4.251) 49(-2.985,-4.751) 50(2.985,-4.751) 51(-2.985,-5.251) 52(2.985,-5.251) 53(-2.985,-5.751) 54(2.985,-5.751) 55(-2.985,-6.251) 56(2.985,-6.251) 57(-2.985,-6.752) 58(2.985,-6.752) 59(-2.985,-7.252) 60(2.985,-7.252)
EBGA-78X78-1667-U58O259T00
  round 0.381 smd: A3(-18.064,-16.642) A5(-18.064,-15.931) A74(-18.064,15.931) A76(-18.064,16.642) AA9(-8.172,-14.166) AA12(-8.172,-12.507) AA14(-8.172,-11.707) AA16(-8.172,-10.907) AA18(-8.172,-10.107) AA19(-8.172,-9.307) AA21(-8.172,-8.506) AA23(-8.172,-7.706) AA25(-8.172,-6.906) AA27(-8.172,-6.106) AA28(-8.172,-5.306) AA30(-8.172,-4.506) AA53(-8.172,5.758) AA55(-8.172,6.558) AA56(-8.172,7.358) AA58(-8.172,8.158) AA60(-8.172,8.959) AA62(-8.172,9.759) AA66(-8.172,11.59) AA69(-8.172,13.307) AA72(-8.172,15.024) AC7(-7.677,-15.024) AC11(-7.677,-13.307) AC12(-7.372,-12.507) AC14(-7.372,-11.707) AC16(-7.372,-10.907) AC18(-7.372,-10.107) AC19(-7.372,-9.307) AC21(-7.372,-8.506) AC23(-7.372,-7.706) AC25(-7.372,-6.906) AC27(-7.372,-6.106) AC28(-7.372,-5.306) AC30(-7.372,-4.506) AC53(-7.372,5.758) AC55(-7.372,6.558) AC56(-7.372,7.358) AC58(-7.372,8.158) AC60(-7.372,8.959) AC62(-7.372,9.759) AC64(-7.677,10.732) AC67(-7.677,12.449) AC71(-7.677,14.166) AD9(-7.182,-14.166) AD66(-7.182,11.59) AD69(-7.182,13.307) AD72(-7.182,15.024) AE7(-6.687,-15.024) AE11(-6.687,-13.307) AE12(-6.572,-12.507) AE14(-6.572,-11.707) AE16(-6.572,-10.907) AE18(-6.572,-10.107) AE19(-6.572,-9.307) AE21(-6.572,-8.506) AE23(-6.572,-7.706) AE25(-6.572,-6.906) AE27(-6.572,-6.106) AE28(-6.572,-5.306) AE30(-6.572,-4.506) AE53(-6.572,5.758) AE55(-6.572,6.558) AE56(-6.572,7.358) AE58(-6.572,8.158) AE60(-6.572,8.959) AE62(-6.572,9.759) AE64(-6.687,10.732) AE67(-6.687,12.449) AE71(-6.687,14.166) AF9(-6.191,-14.166) AF66(-6.191,11.59) AF69(-6.191,13.307) AF72(-6.191,15.024) AG7(-5.696,-15.024) AG11(-5.696,-13.307) AG12(-5.772,-12.507) AG14(-5.772,-11.707) AG16(-5.772,-10.907) AG18(-5.772,-10.107) AG19(-5.772,-9.307) AG21(-5.772,-8.506) AG23(-5.772,-7.706) AG25(-5.772,-6.906) AG27(-5.772,-6.106) AG28(-5.772,-5.306) AG30(-5.772,-4.506) AG53(-5.772,5.758) AG55(-5.772,6.558) AG56(-5.772,7.358) AG58(-5.772,8.158) AG60(-5.772,8.959) AG62(-5.772,9.759) AG64(-5.696,10.732) AG67(-5.696,12.449) AG71(-5.696,14.166) AH9(-5.201,-14.166) AH12(-4.972,-12.507) AH14(-4.972,-11.707) AH16(-4.972,-10.907) AH18(-4.972,-10.107) AH19(-4.972,-9.307) AH21(-4.972,-8.506) AH23(-4.972,-7.706) AH25(-4.972,-6.906) AH27(-4.972,-6.106) AH28(-4.972,-5.306) AH30(-4.972,-4.506) AH53(-4.972,5.758) AH55(-4.972,6.558) AH56(-4.972,7.358) AH58(-4.972,8.158) AH60(-4.972,8.959) AH62(-4.972,9.759) AH66(-5.201,11.59) AH69(-5.201,13.307) AH72(-5.201,15.024) AJ7(-4.705,-15.024) AJ11(-4.705,-13.307) AJ64(-4.705,10.732) AJ67(-4.705,12.449) AJ71(-4.705,14.166) AK9(-4.21,-14.166) AK12(-4.172,-12.507) AK14(-4.172,-11.707) AK16(-4.172,-10.907) AK18(-4.172,-10.107) AK19(-4.172,-9.307) AK21(-4.172,-8.506) AK23(-4.172,-7.706) AK25(-4.172,-6.906) AK27(-4.172,-6.106) AK28(-4.172,-5.306) AK30(-4.172,-4.506) AK53(-4.172,5.758) AK55(-4.172,6.558) AK56(-4.172,7.358) AK58(-4.172,8.158) AK60(-4.172,8.959) AK62(-4.172,9.759) AK66(-4.21,11.59) AK69(-4.21,13.307) AK72(-4.21,15.024) AL7(-3.715,-15.024) AL11(-3.715,-13.307) AL64(-3.715,10.732) AL67(-3.715,12.449) AL71(-3.715,14.166) AM9(-3.219,-14.166) AM12(-3.372,-12.507) AM14(-3.372,-11.707) AM16(-3.372,-10.907) AM18(-3.372,-10.107) AM19(-3.372,-9.307) AM21(-3.372,-8.506) AM23(-3.372,-7.706) AM25(-3.372,-6.906) AM27(-3.372,-6.106) AM28(-3.372,-5.306) AM30(-3.372,-4.506) AM53(-3.372,5.758) AM55(-3.372,6.558) AM56(-3.372,7.358) AM58(-3.372,8.158) AM60(-3.372,8.959) AM62(-3.372,9.759) AM66(-3.219,11.59) AM69(-3.219,13.307) AM72(-3.219,15.024) AN7(-2.724,-15.024) AN11(-2.724,-13.307) AN64(-2.724,10.732) AN67(-2.724,12.449) AN71(-2.724,14.166) AP9(-2.229,-14.166) AP12(-2.572,-12.507) AP14(-2.572,-11.707) AP16(-2.572,-10.907) AP18(-2.572,-10.107) AP19(-2.572,-9.307) AP21(-2.572,-8.506) AP23(-2.572,-7.706) AP25(-2.572,-6.906) AP27(-2.572,-6.106) AP28(-2.572,-5.306) AP30(-2.572,-4.506) AP53(-2.572,5.758) AP55(-2.572,6.558) AP56(-2.572,7.358) AP58(-2.572,8.158) AP60(-2.572,8.959) AP62(-2.572,9.759) AP66(-2.229,11.59) AP69(-2.229,13.307) AP72(-2.229,15.024) AR7(-1.734,-15.024) AR11(-1.734,-13.307) AR12(-1.772,-12.507) AR14(-1.772,-11.707) AR16(-1.772,-10.907) AR18(-1.772,-10.107) AR19(-1.772,-9.307) AR21(-1.772,-8.506) AR23(-1.772,-7.706) AR25(-1.772,-6.906) AR27(-1.772,-6.106) AR28(-1.772,-5.306) AR30(-1.772,-4.506) AR53(-1.772,5.758) AR55(-1.772,6.558) AR56(-1.775,7.358) AR60(-1.734,9.014) AR64(-1.734,10.732) AR67(-1.734,12.449) AR71(-1.734,14.166) AU9(-1.238,-14.166) AU12(-0.972,-12.507) AU14(-0.972,-11.707) AU16(-0.972,-10.907) AU18(-0.972,-10.107) AU19(-0.972,-9.307) AU21(-0.972,-8.506) AU23(-0.972,-7.706) AU25(-0.972,-6.906) AU27(-0.972,-6.106) AU28(-0.972,-5.306) AU30(-0.972,-4.506) AU53(-0.972,5.758) AU55(-0.972,6.558) AU56(-0.975,7.358) AU58(-1.238,8.156) AU62(-1.238,9.873) AU66(-1.238,11.59) AU69(-1.238,13.307) AU72(-1.238,15.024) AV7(-0.743,-15.024) AV11(-0.743,-13.307) AV60(-0.743,9.014) AV64(-0.743,10.732) AV67(-0.743,12.449) AV71(-0.743,14.166) AW9(-0.248,-14.166) AW12(-0.171,-12.507) AW14(-0.171,-11.707) AW16(-0.171,-10.907) AW18(-0.171,-10.107) AW19(-0.171,-9.307) AW21(-0.171,-8.506) AW23(-0.171,-7.706) AW25(-0.171,-6.906) AW27(-0.171,-6.106) AW28(-0.171,-5.306) AW30(-0.171,-4.506) AW55(-0.171,6.558) AW56(-0.174,7.358) AW58(-0.248,8.156) AW62(-0.248,9.873) AW66(-0.248,11.59) AW69(-0.248,13.307) AW72(-0.248,15.024) AY7(0.248,-15.024) AY11(0.248,-13.307) AY60(0.248,9.014) AY64(0.248,10.732) AY67(0.248,12.449) AY71(0.248,14.166) B2(-17.353,-17.353) B77(-17.353,17.353) BA9(0.743,-14.166) BA12(0.629,-12.507) BA14(0.629,-11.707) BA16(0.629,-10.907) BA18(0.629,-10.107) BA19(0.629,-9.307) BA21(0.629,-8.506) BA23(0.629,-7.706) BA25(0.629,-6.906) BA27(0.629,-6.106) BA28(0.629,-5.306) BA30(0.629,-4.506) BA56(0.626,7.358) BA58(0.743,8.156) BA62(0.743,9.873) BA66(0.743,11.59) BA69(0.743,13.307) BA72(0.743,15.024) BB7(1.238,-15.024) BB11(1.238,-13.307) BB12(1.429,-12.507) BB14(1.429,-11.707) BB16(1.429,-10.907) BB18(1.429,-10.107) BB19(1.429,-9.307) BB21(1.429,-8.506) BB23(1.429,-7.706) BB25(1.429,-6.906) BB27(1.429,-6.106) BB28(1.429,-5.306) BB30(1.429,-4.506) BB32(1.429,-3.806) BB33(1.429,-3.106) BB35(1.429,-2.406) BB36(1.429,-1.672) BB56(1.426,7.358) BB60(1.238,9.014) BB64(1.238,10.732) BB67(1.238,12.449) BB71(1.238,14.166) BC9(1.734,-14.166) BC58(1.734,8.156) BC62(1.734,9.873) BC66(1.734,11.59) BC69(1.734,13.307) BC72(1.734,15.024) BD7(2.229,-15.024) BD11(2.229,-13.307) BD14(2.229,-11.59) BD18(2.229,-9.873) BD22(2.229,-8.156) BD26(2.229,-6.439) BD30(2.229,-4.722) BD33(2.229,-3.005) BD36(2.029,-2.039) BD37(2.026,-1.306) BD56(2.226,7.358) BD60(2.229,9.014) BD64(2.229,10.732) BD67(2.229,12.449) BD71(2.229,14.166) BE9(2.724,-14.166) BE13(2.724,-12.449) BE16(2.724,-10.732) BE20(2.724,-9.014) BE24(2.724,-7.297) BE28(2.724,-5.58) BE32(2.724,-3.863) BE35(2.724,-2.146) BE37(2.726,-1.306) BE58(2.724,8.156) BE62(2.724,9.873) BE66(2.724,11.59) BE69(2.724,13.307) BE72(2.724,15.024) BF7(3.219,-15.024) BF11(3.219,-13.307) BF14(3.219,-11.59) BF18(3.219,-9.873) BF22(3.219,-8.156) BF26(3.219,-6.439) BF30(3.219,-4.722) BF33(3.219,-3.005) BF56(3.026,7.358) BF60(3.219,9.014) BF64(3.219,10.732) BF67(3.219,12.449) BF71(3.219,14.166) BG9(3.715,-14.166) BG13(3.715,-12.449) BG16(3.715,-10.732) BG20(3.715,-9.014) BG24(3.715,-7.297) BG28(3.715,-5.58) BG32(3.715,-3.863) BG35(3.715,-2.146) BG37(3.426,-1.306) BG58(3.715,8.156) BG62(3.715,9.873) BG66(3.715,11.59) BG69(3.715,13.307) BG72(3.715,15.024) BH7(4.21,-15.024) BH11(4.21,-13.307) BH14(4.21,-11.59) BH18(4.21,-9.873) BH22(4.21,-8.156) BH26(4.21,-6.439) BH30(4.21,-4.722) BH33(4.21,-3.005) BH37(4.126,-1.306) BH56(3.826,7.358) BH60(4.21,9.014) BH64(4.21,10.732) BH67(4.21,12.449) BH71(4.21,14.166) BJ9(4.705,-14.166) BJ13(4.705,-12.449) BJ16(4.705,-10.732) BJ20(4.705,-9.014) BJ24(4.705,-7.297) BJ28(4.705,-5.58) BJ32(4.705,-3.863) BJ35(4.705,-2.146) BJ56(4.626,7.358) BJ58(4.705,8.156) BJ62(4.705,9.873) BJ66(4.705,11.59) BJ69(4.705,13.307) BJ72(4.705,15.024) BK37(4.826,-1.306) BL7(5.201,-15.024) BL11(5.201,-13.307) BL14(5.201,-11.59) BL18(5.201,-9.873) BL22(5.201,-8.156) BL26(5.201,-6.439) BL30(5.201,-4.722) BL33(5.201,-3.005) BL37(5.526,-1.306) BL56(5.426,7.358) BL60(5.201,9.014) BL64(5.201,10.732) BL67(5.201,12.449) BL71(5.201,14.166) BM9(5.696,-14.166) BM13(5.696,-12.449) BM16(5.696,-10.732) BM20(5.696,-9.014) BM24(5.696,-7.297) BM28(5.696,-5.58) BM32(5.696,-3.863) BM35(5.696,-2.146) BM58(5.696,8.156) BM62(5.696,9.873) BM66(5.696,11.59) BM69(5.696,13.307) BM72(5.696,15.024) BN7(6.191,-15.024) BN11(6.191,-13.307) BN14(6.191,-11.59) BN18(6.191,-9.873) BN22(6.191,-8.156) BN26(6.191,-6.439) BN30(6.191,-4.722) BN33(6.191,-3.005) BN37(6.226,-1.306) BN56(6.226,7.358) BN60(6.191,9.014) BN64(6.191,10.732) BN67(6.191,12.449) BN71(6.191,14.166) BP9(6.687,-14.166) BP13(6.687,-12.449) BP16(6.687,-10.732) BP20(6.687,-9.014) BP24(6.687,-7.297) BP28(6.687,-5.58) BP32(6.687,-3.863) BP35(6.687,-2.146) BP37(6.926,-1.306) BP56(7.026,7.358) BP58(6.687,8.156) BP62(6.687,9.873) BP66(6.687,11.59) BP69(6.687,13.307) BP72(6.687,15.024) BR7(7.182,-15.024) BR11(7.182,-13.307) BR14(7.182,-11.59) BR18(7.182,-9.873) BR22(7.182,-8.156) BR26(7.182,-6.439) BR30(7.182,-4.722) BR33(7.182,-3.005) BR60(7.182,9.014) BR64(7.182,10.732) BR67(7.182,12.449) BR71(7.182,14.166) BT9(7.677,-14.166) BT13(7.677,-12.449) BT16(7.677,-10.732) BT20(7.677,-9.014) BT24(7.677,-7.297) BT28(7.677,-5.58) BT32(7.677,-3.863) BT35(7.677,-2.146) BT37(7.627,-1.306) BT56(7.727,7.358) BT58(7.677,8.156) BT62(7.677,9.873) BT66(7.677,11.59) BT69(7.677,13.307) BT72(7.677,15.024) BU7(8.172,-15.024) BU11(8.172,-13.307) BU14(8.172,-11.59) BU18(8.172,-9.873) BU22(8.172,-8.156) BU26(8.172,-6.439) BU30(8.172,-4.722) BU33(8.172,-3.005) BU37(8.327,-1.306) BU60(8.172,9.014) BU64(8.172,10.732) BU67(8.172,12.449) BU71(8.172,14.166) BV9(8.668,-14.166) BV13(8.668,-12.449) BV16(8.668,-10.732) BV20(8.668,-9.014) BV24(8.668,-7.297) BV28(8.668,-5.58) BV32(8.668,-3.863) BV35(8.668,-2.146) BV56(8.427,7.358) BV58(8.668,8.156) BV62(8.668,9.873) BV66(8.668,11.59) BV69(8.668,13.307) BV72(8.668,15.024) BW7(9.163,-15.024) BW11(9.163,-13.307) BW14(9.163,-11.59) BW18(9.163,-9.873) BW22(9.163,-8.156) BW26(9.163,-6.439) BW30(9.163,-4.722) BW33(9.163,-3.005) BW37(9.027,-1.306) BW39(8.958,-0.607) BW40(8.958,0.093) BW42(8.958,0.793) BW43(8.958,1.493) BW45(9.258,2.226) BW47(9.258,3.026) BW49(9.258,3.827) BW50(9.258,4.627) BW52(9.158,5.427) BW54(8.958,6.127) BW55(8.958,6.877) BW60(9.163,9.014) BW64(9.163,10.732) BW67(9.163,12.449) BW71(9.163,14.166) BY9(9.658,-14.166) BY13(9.658,-12.449) BY16(9.658,-10.732) BY20(9.658,-9.014) BY24(9.658,-7.297) BY28(9.658,-5.58) BY32(9.658,-3.863) BY35(9.658,-2.146) BY39(9.658,-0.429) BY43(9.658,1.288) BY54(9.658,6.439) BY58(9.658,8.156) BY62(9.658,9.873) BY66(9.658,11.59) BY69(9.658,13.307) BY72(9.658,15.024) C1(-16.642,-18.064) C78(-16.642,18.064) CA7(10.154,-15.024) CA11(10.154,-13.307) CA14(10.154,-11.59) CA18(10.154,-9.873) CA22(10.154,-8.156) CA26(10.154,-6.439) CA30(10.154,-4.722) CA33(10.154,-3.005) CA37(10.154,-1.288) CA41(10.154,0.429) CA45(10.154,2.146) CA46(9.943,2.84) CA49(10.154,3.863) CA51(9.943,4.887) CA52(10.154,5.58) CA56(10.154,7.297) CA60(10.154,9.014) CA64(10.154,10.732) CA67(10.154,12.449) CA71(10.154,14.166) CB9(10.649,-14.166) CB13(10.649,-12.449) CB16(10.649,-10.732) CB20(10.649,-9.014) CB24(10.649,-7.297) CB28(10.649,-5.58) CB32(10.649,-3.863) CB35(10.649,-2.146) CB39(10.649,-0.429) CB43(10.649,1.288) CB47(10.649,3.005) CB51(10.649,4.722) CB54(10.649,6.439) CB58(10.649,8.156) CB62(10.649,9.873) CB66(10.649,11.59) CB69(10.649,13.307) CB72(10.649,15.024) CC7(11.144,-15.024) CC11(11.144,-13.307) CC14(11.144,-11.59) CC18(11.144,-9.873) CC22(11.144,-8.156) CC26(11.144,-6.439) CC30(11.144,-4.722) CC33(11.144,-3.005) CC37(11.144,-1.288) CC41(11.144,0.429) CC45(11.144,2.146) CC49(11.144,3.863) CC52(11.144,5.58) CC56(11.144,7.297) CC60(11.144,9.014) CC64(11.144,10.732) CC67(11.144,12.449) CC71(11.144,14.166) CD9(11.64,-14.166) CD13(11.64,-12.449) CD16(11.64,-10.732) CD20(11.64,-9.014) CD24(11.64,-7.297) CD28(11.64,-5.58) CD32(11.64,-3.863) CD35(11.64,-2.146) CD39(11.64,-0.429) CD43(11.64,1.288) CD47(11.64,3.005) CD51(11.64,4.722) CD54(11.64,6.439) CD58(11.64,8.156) CD62(11.64,9.873) CD66(11.64,11.59) CD69(11.64,13.307) CD72(11.64,15.024) CF7(12.135,-15.024) CF11(12.135,-13.307) CF14(12.135,-11.59) CF18(12.135,-9.873) CF22(12.135,-8.156) CF26(12.135,-6.439) CF30(12.135,-4.722) CF33(12.135,-3.005) CF37(12.135,-1.288) CF41(12.135,0.429) CF45(12.135,2.146) CF49(12.135,3.863) CF52(12.135,5.58) CF56(12.135,7.297) CF60(12.135,9.014) CF64(12.135,10.732) CF67(12.135,12.449) CF71(12.135,14.166) CG9(12.63,-14.166) CG13(12.63,-12.449) CG16(12.63,-10.732) CG20(12.63,-9.014) CG24(12.63,-7.297) CG28(12.63,-5.58) CG32(12.63,-3.863) CG35(12.63,-2.146) CG39(12.63,-0.429) CG43(12.63,1.288) CG47(12.63,3.005) CG51(12.63,4.722) CG54(12.63,6.439) CG58(12.63,8.156) CG62(12.63,9.873) CG66(12.63,11.59) CG69(12.63,13.307) CG72(12.63,15.024) CH7(13.125,-15.024) CH11(13.125,-13.307) CH14(13.125,-11.59) CH18(13.125,-9.873) CH22(13.125,-8.156) CH26(13.125,-6.439) CH30(13.125,-4.722) CH33(13.125,-3.005) CH37(13.125,-1.288) CH41(13.125,0.429) CH45(13.125,2.146) CH49(13.125,3.863) CH52(13.125,5.58) CH56(13.125,7.297) CH60(13.125,9.014) CH64(13.125,10.732) CH67(13.125,12.449) CH71(13.125,14.166) CJ9(13.621,-14.166) CJ13(13.621,-12.449) CJ16(13.621,-10.732) CJ20(13.621,-9.014) CJ24(13.621,-7.297) CJ28(13.621,-5.58) CJ32(13.621,-3.863) CJ35(13.621,-2.146) CJ39(13.621,-0.429) CJ43(13.621,1.288) CJ47(13.621,3.005) CJ51(13.621,4.722) CJ54(13.621,6.439) CJ58(13.621,8.156) CJ62(13.621,9.873) CJ66(13.621,11.59) CJ69(13.621,13.307) CJ72(13.621,15.024) CK7(14.116,-15.024) CK11(14.116,-13.307) CK14(14.116,-11.59) CK18(14.116,-9.873) CK22(14.116,-8.156) CK26(14.116,-6.439) CK30(14.116,-4.722) CK33(14.116,-3.005) CK37(14.116,-1.288) CK41(14.116,0.429) CK45(14.116,2.146) CK49(14.116,3.863) CK52(14.116,5.58) CK56(14.116,7.297) CK60(14.116,9.014) CK64(14.116,10.732) CK67(14.116,12.449) CK71(14.116,14.166) CL9(14.611,-14.166) CL13(14.611,-12.449) CL16(14.611,-10.732) CL20(14.611,-9.014) CL24(14.611,-7.297) CL28(14.611,-5.58) CL32(14.611,-3.863) CL35(14.611,-2.146) CL39(14.611,-0.429) CL43(14.611,1.288) CL47(14.611,3.005) CL51(14.611,4.722) CL54(14.611,6.439) CL58(14.611,8.156) CL62(14.611,9.873) CL66(14.611,11.59) CL69(14.611,13.307) CL72(14.611,15.024) CM7(15.107,-15.024) CM11(15.107,-13.307) CM14(15.107,-11.59) CM18(15.107,-9.873) CM22(15.107,-8.156) CM26(15.107,-6.439) CM30(15.107,-4.722) CM33(15.107,-3.005) CM37(15.107,-1.288) CM41(15.107,0.429) CM45(15.107,2.146) CM49(15.107,3.863) CM52(15.107,5.58) CM56(15.107,7.297) CM60(15.107,9.014) CM64(15.107,10.732) CM67(15.107,12.449) CM71(15.107,14.166) CP1(15.931,-18.064) CP78(15.931,18.064) CR1(16.642,-18.064) CR78(16.642,18.064) CU2(17.353,-17.353) CU77(17.353,17.353) CV3(18.064,-16.642) CV5(18.064,-15.931) CV74(18.064,15.931) CV76(18.064,16.642) E1(-15.931,-18.064) E78(-15.931,18.064) F9(-15.107,-14.166) F13(-15.107,-12.449) F16(-15.107,-10.732) F20(-15.107,-9.014) F24(-15.107,-7.297) F28(-15.107,-5.58) F32(-15.107,-3.863) F35(-15.107,-2.146) F39(-15.107,-0.429) F43(-15.107,1.288) F47(-15.107,3.005) F51(-15.107,4.722) F54(-15.107,6.439) F58(-15.107,8.156) F62(-15.107,9.873) F66(-15.107,11.59) F69(-15.107,13.307) F72(-15.107,15.024) H7(-14.611,-15.024) H11(-14.611,-13.307) H14(-14.611,-11.59) H18(-14.611,-9.873) H22(-14.611,-8.156) H26(-14.611,-6.439) H30(-14.611,-4.722) H33(-14.611,-3.005) H37(-14.611,-1.288) H41(-14.611,0.429) H45(-14.611,2.146) H49(-14.611,3.863) H52(-14.611,5.58) H56(-14.611,7.297) H60(-14.611,9.014) H64(-14.611,10.732) H67(-14.611,12.449) H71(-14.611,14.166) J9(-14.116,-14.166) J13(-14.116,-12.449) J16(-14.116,-10.732) J20(-14.116,-9.014) J24(-14.116,-7.297) J28(-14.116,-5.58) J32(-14.116,-3.863) J35(-14.116,-2.146) J39(-14.116,-0.429) J43(-14.116,1.288) J47(-14.116,3.005) J51(-14.116,4.722) J54(-14.116,6.439) J58(-14.116,8.156) J62(-14.116,9.873) J66(-14.116,11.59) J69(-14.116,13.307) J72(-14.116,15.024) K7(-13.621,-15.024) K11(-13.621,-13.307) K14(-13.621,-11.59) K18(-13.621,-9.873) K22(-13.621,-8.156) K26(-13.621,-6.439) K30(-13.621,-4.722) K33(-13.621,-3.005) K37(-13.621,-1.288) K41(-13.621,0.429) K45(-13.621,2.146) K49(-13.621,3.863) K52(-13.621,5.58) K56(-13.621,7.297) K60(-13.621,9.014) K64(-13.621,10.732) K67(-13.621,12.449) K71(-13.621,14.166) L9(-13.125,-14.166) L13(-13.125,-12.449) L16(-13.125,-10.732) L20(-13.125,-9.014) L24(-13.125,-7.297) L28(-13.125,-5.58) L32(-13.125,-3.863) L35(-13.125,-2.146) L39(-13.125,-0.429) L43(-13.125,1.288) L47(-13.125,3.005) L51(-13.125,4.722) L54(-13.125,6.439) L58(-13.125,8.156) L62(-13.125,9.873) L66(-13.125,11.59) L69(-13.125,13.307) L72(-13.125,15.024) M7(-12.63,-15.024) M11(-12.63,-13.307) M14(-12.63,-11.59) M18(-12.63,-9.873) M22(-12.63,-8.156) M26(-12.63,-6.439) M30(-12.63,-4.722) M33(-12.63,-3.005) M37(-12.63,-1.288) M41(-12.63,0.429) M45(-12.63,2.146) M49(-12.63,3.863) M52(-12.63,5.58) M56(-12.63,7.297) M60(-12.63,9.014) M64(-12.63,10.732) M67(-12.63,12.449) M71(-12.63,14.166) N9(-12.135,-14.166) N13(-12.135,-12.449) N16(-12.135,-10.732) N20(-12.135,-9.014) N24(-12.135,-7.297) N28(-12.135,-5.58) N32(-12.135,-3.863) N35(-12.135,-2.146) N39(-12.135,-0.429) N43(-12.135,1.288) N47(-12.135,3.005) N51(-12.135,4.722) N54(-12.135,6.439) N58(-12.135,8.156) N62(-12.135,9.873) N66(-12.135,11.59) N69(-12.135,13.307) N72(-12.135,15.024) P7(-11.64,-15.024) P11(-11.64,-13.307) P14(-11.64,-11.59) P18(-11.64,-9.873) P22(-11.64,-8.156) P26(-11.64,-6.439) P30(-11.64,-4.722) P33(-11.64,-3.005) P52(-11.64,5.58) P56(-11.64,7.297) P60(-11.64,9.014) P64(-11.64,10.732) P67(-11.64,12.449) P71(-11.64,14.166) R9(-11.144,-14.166) R13(-11.144,-12.449) R16(-11.144,-10.732) R20(-11.144,-9.014) R24(-11.144,-7.297) R28(-11.144,-5.58) R32(-11.144,-3.863) R35(-11.373,-2.243) R37(-11.373,-1.443) R39(-11.373,-0.643) R40(-11.373,0.157) R42(-11.373,0.958) R44(-11.373,1.758) R46(-11.373,2.558) R48(-11.373,3.358) R49(-11.373,4.158) R54(-11.144,6.439) R58(-11.144,8.156) R62(-11.144,9.873) R66(-11.144,11.59) R69(-11.144,13.307) R72(-11.144,15.024) T7(-10.649,-15.024) T11(-10.649,-13.307) T14(-10.649,-11.59) T18(-10.649,-9.873) T22(-10.649,-8.156) T26(-10.649,-6.439) T30(-10.649,-4.722) T33(-10.649,-3.005) T35(-10.573,-2.243) T37(-10.573,-1.443) T39(-10.573,-0.643) T40(-10.573,0.157) T42(-10.573,0.958) T44(-10.573,1.758) T46(-10.573,2.558) T48(-10.573,3.358) T49(-10.573,4.158) T51(-10.573,4.958) T53(-10.573,5.758) T56(-10.649,7.297) T60(-10.649,9.014) T64(-10.649,10.732) T67(-10.649,12.449) T71(-10.649,14.166) U9(-10.154,-14.166) U13(-10.154,-12.449) U16(-10.154,-10.732) U20(-10.154,-9.014) U24(-10.154,-7.297) U28(-10.154,-5.58) U32(-10.154,-3.863) U66(-10.154,11.59) U69(-10.154,13.307) U72(-10.154,15.024) V7(-9.658,-15.024) V11(-9.658,-13.307) V14(-9.658,-11.59) V18(-9.658,-9.873) V22(-9.658,-8.156) V26(-9.658,-6.439) V30(-9.658,-4.722) V33(-9.773,-3.043) V35(-9.773,-2.243) V37(-9.773,-1.443) V39(-9.773,-0.643) V40(-9.773,0.157) V42(-9.773,0.958) V44(-9.773,1.758) V46(-9.773,2.558) V48(-9.773,3.358) V49(-9.773,4.158) V51(-9.773,4.958) V53(-9.773,5.758) V55(-9.773,6.558) V56(-9.773,7.358) V58(-9.773,8.158) V60(-9.773,8.959) V62(-9.773,9.759) V64(-9.658,10.732) V67(-9.658,12.449) V71(-9.658,14.166) W9(-9.163,-14.166) W13(-9.163,-12.449) W16(-9.163,-10.732) W20(-9.163,-9.014) W24(-9.163,-7.297) W28(-9.163,-5.58) W66(-9.163,11.59) W69(-9.163,13.307) W72(-9.163,15.024) Y7(-8.668,-15.024) Y11(-8.668,-13.307) Y30(-8.898,-4.506) Y32(-8.973,-3.778) Y33(-8.973,-3.043) Y35(-8.973,-2.243) Y37(-8.973,-1.443) Y39(-8.973,-0.643) Y40(-8.973,0.157) Y42(-8.973,0.958) Y53(-8.973,5.758) Y55(-8.973,6.558) Y56(-8.973,7.358) Y58(-8.973,8.158) Y60(-8.973,8.959) Y62(-8.973,9.759) Y64(-8.668,10.732) Y67(-8.668,12.449) Y71(-8.668,14.166)
  round 0.356 smd: A6(-18.064,-15.219) A73(-18.064,15.219) AA2(-8.416,-17.327) AA4(-8.416,-16.337) AA75(-8.416,16.337) AA77(-8.416,17.327) AB3(-7.921,-16.832) AB5(-7.921,-15.842) AB74(-7.921,15.842) AB76(-7.921,16.832) AC2(-7.426,-17.327) AC4(-7.426,-16.337) AC75(-7.426,16.337) AC77(-7.426,17.327) AD3(-6.931,-16.832) AD5(-6.931,-15.842) AD74(-6.931,15.842) AD76(-6.931,16.832) AE2(-6.436,-17.327) AE4(-6.436,-16.337) AE75(-6.436,16.337) AE77(-6.436,17.327) AF3(-5.941,-16.832) AF5(-5.941,-15.842) AF74(-5.941,15.842) AF76(-5.941,16.832) AG2(-5.446,-17.327) AG4(-5.446,-16.337) AG75(-5.446,16.337) AG77(-5.446,17.327) AH3(-4.95,-16.832) AH5(-4.95,-15.842) AH74(-4.95,15.842) AH76(-4.95,16.832) AK2(-4.455,-17.327) AK4(-4.455,-16.337) AK75(-4.455,16.337) AK77(-4.455,17.327) AL3(-3.96,-16.832) AL5(-3.96,-15.842) AL74(-3.96,15.842) AL76(-3.96,16.832) AM2(-3.465,-17.327) AM4(-3.465,-16.337) AM75(-3.465,16.337) AM77(-3.465,17.327) AN3(-2.97,-16.832) AN5(-2.97,-15.842) AN74(-2.97,15.842) AN76(-2.97,16.832) AP2(-2.475,-17.327) AP4(-2.475,-16.337) AP75(-2.475,16.337) AP77(-2.475,17.327) AR3(-1.98,-16.832) AR5(-1.98,-15.842) AR74(-1.98,15.842) AR76(-1.98,16.832) AT2(-1.485,-17.327) AT4(-1.485,-16.337) AT75(-1.485,16.337) AT77(-1.485,17.327) AU3(-0.99,-16.832) AU5(-0.99,-15.842) AU74(-0.99,15.842) AU76(-0.99,16.832) AV2(-0.495,-17.327) AV4(-0.495,-16.337) AV75(-0.495,16.337) AV77(-0.495,17.327) AW3(0,-16.832) AW5(0,-15.842) AW74(0,15.842) AW76(0,16.832) AY2(0.495,-17.327) AY4(0.495,-16.337) AY75(0.495,16.337) AY77(0.495,17.327) B3(-17.353,-16.642) B10(-17.327,-13.366) B13(-17.327,-12.376) B15(-17.327,-11.386) B17(-17.327,-10.396) B19(-17.327,-9.406) B21(-17.327,-8.416) B24(-17.327,-7.426) B26(-17.327,-6.436) B28(-17.327,-5.446) B30(-17.327,-4.455) B32(-17.327,-3.465) B35(-17.327,-2.475) B37(-17.327,-1.485) B39(-17.327,-0.495) B41(-17.327,0.495) B43(-17.327,1.485) B46(-17.327,2.475) B48(-17.327,3.465) B50(-17.327,4.455) B52(-17.327,5.446) B54(-17.327,6.436) B57(-17.327,7.426) B59(-17.327,8.416) B61(-17.327,9.406) B63(-17.327,10.396) B65(-17.327,11.386) B67(-17.327,12.376) B69(-17.327,13.366) B76(-17.353,16.642) BA3(0.99,-16.832) BA5(0.99,-15.842) BA74(0.99,15.842) BA76(0.99,16.832) BB2(1.485,-17.327) BB4(1.485,-16.337) BB75(1.485,16.337) BB77(1.485,17.327) BD3(1.98,-16.832) BD5(1.98,-15.842) BD74(1.98,15.842) BD76(1.98,16.832) BE2(2.475,-17.327) BE4(2.475,-16.337) BE75(2.475,16.337) BE77(2.475,17.327) BF3(2.97,-16.832) BF5(2.97,-15.842) BF74(2.97,15.842) BF76(2.97,16.832) BG2(3.465,-17.327) BG4(3.465,-16.337) BG75(3.465,16.337) BG77(3.465,17.327) BH3(3.96,-16.832) BH5(3.96,-15.842) BH74(3.96,15.842) BH76(3.96,16.832) BJ2(4.455,-17.327) BJ4(4.455,-16.337) BJ75(4.455,16.337) BJ77(4.455,17.327) BK3(4.95,-16.832) BK5(4.95,-15.842) BK74(4.95,15.842) BK76(4.95,16.832) BL2(5.446,-17.327) BL4(5.446,-16.337) BL75(5.446,16.337) BL77(5.446,17.327) BM3(5.941,-16.832) BM5(5.941,-15.842) BM74(5.941,15.842) BM76(5.941,16.832) BN2(6.436,-17.327) BN4(6.436,-16.337) BN75(6.436,16.337) BN77(6.436,17.327) BP3(6.931,-16.832) BP5(6.931,-15.842) BP74(6.931,15.842) BP76(6.931,16.832) BR2(7.426,-17.327) BR4(7.426,-16.337) BR75(7.426,16.337) BR77(7.426,17.327) BT3(7.921,-16.832) BT5(7.921,-15.842) BT74(7.921,15.842) BT76(7.921,16.832) BU2(8.416,-17.327) BU4(8.416,-16.337) BU75(8.416,16.337) BU77(8.416,17.327) BW3(8.911,-16.832) BW5(8.911,-15.842) BW74(8.911,15.842) BW76(8.911,16.832) BY2(9.406,-17.327) BY4(9.406,-16.337) BY75(9.406,16.337) BY77(9.406,17.327) C2(-16.642,-17.353) C9(-16.832,-13.861) C12(-16.832,-12.871) C14(-16.832,-11.881) C16(-16.832,-10.891) C18(-16.832,-9.901) C20(-16.832,-8.911) C23(-16.832,-7.921) C25(-16.832,-6.931) C27(-16.832,-5.941) C29(-16.832,-4.95) C31(-16.832,-3.96) C34(-16.832,-2.97) C36(-16.832,-1.98) C38(-16.832,-0.99) C40(-16.832,0) C42(-16.832,0.99) C44(-16.832,1.98) C47(-16.832,2.97) C49(-16.832,3.96) C51(-16.832,4.95) C53(-16.832,5.941) C55(-16.832,6.931) C58(-16.832,7.921) C60(-16.832,8.911) C62(-16.832,9.901) C64(-16.832,10.891) C66(-16.832,11.881) C68(-16.832,12.871) C70(-16.832,13.861) C77(-16.642,17.353) CA3(9.901,-16.832) CA5(9.901,-15.842) CA74(9.901,15.842) CA76(9.901,16.832) CB2(10.396,-17.327) CB4(10.396,-16.337) CB75(10.396,16.337) CB77(10.396,17.327) CC3(10.891,-16.832) CC5(10.891,-15.842) CC74(10.891,15.842) CC76(10.891,16.832) CD2(11.386,-17.327) CD4(11.386,-16.337) CD75(11.386,16.337) CD77(11.386,17.327) CE3(11.881,-16.832) CE5(11.881,-15.842) CE74(11.881,15.842) CE76(11.881,16.832) CF2(12.376,-17.327) CF4(12.376,-16.337) CF75(12.376,16.337) CF77(12.376,17.327) CG3(12.871,-16.832) CG5(12.871,-15.842) CG74(12.871,15.842) CG76(12.871,16.832) CH2(13.366,-17.327) CH4(13.366,-16.337) CH75(13.366,16.337) CH77(13.366,17.327) CJ3(13.861,-16.832) CJ5(13.861,-15.842) CJ74(13.861,15.842) CJ76(13.861,16.832) CK4(14.356,-16.337) CK75(14.356,16.337) CM1(15.219,-18.064) CM78(15.219,18.064) CP9(15.842,-13.861) CP12(15.842,-12.871) CP14(15.842,-11.881) CP16(15.842,-10.891) CP18(15.842,-9.901) CP20(15.842,-8.911) CP23(15.842,-7.921) CP25(15.842,-6.931) CP27(15.842,-5.941) CP29(15.842,-4.95) CP31(15.842,-3.96) CP34(15.842,-2.97) CP36(15.842,-1.98) CP38(15.842,-0.99) CP40(15.842,0) CP42(15.842,0.99) CP44(15.842,1.98) CP47(15.842,2.97) CP49(15.842,3.96) CP51(15.842,4.95) CP53(15.842,5.941) CP55(15.842,6.931) CP58(15.842,7.921) CP60(15.842,8.911) CP62(15.842,9.901) CP64(15.842,10.891) CP66(15.842,11.881) CP68(15.842,12.871) CP70(15.842,13.861) CR2(16.642,-17.353) CR8(16.337,-14.356) CR10(16.337,-13.366) CR13(16.337,-12.376) CR15(16.337,-11.386) CR17(16.337,-10.396) CR19(16.337,-9.406) CR21(16.337,-8.416) CR24(16.337,-7.426) CR26(16.337,-6.436) CR28(16.337,-5.446) CR30(16.337,-4.455) CR32(16.337,-3.465) CR35(16.337,-2.475) CR37(16.337,-1.485) CR39(16.337,-0.495) CR41(16.337,0.495) CR43(16.337,1.485) CR46(16.337,2.475) CR48(16.337,3.465) CR50(16.337,4.455) CR52(16.337,5.446) CR54(16.337,6.436) CR57(16.337,7.426) CR59(16.337,8.416) CR61(16.337,9.406) CR63(16.337,10.396) CR65(16.337,11.386) CR67(16.337,12.376) CR69(16.337,13.366) CR71(16.337,14.356) CR77(16.642,17.353) CT9(16.832,-13.861) CT12(16.832,-12.871) CT14(16.832,-11.881) CT16(16.832,-10.891) CT18(16.832,-9.901) CT20(16.832,-8.911) CT23(16.832,-7.921) CT25(16.832,-6.931) CT27(16.832,-5.941) CT29(16.832,-4.95) CT31(16.832,-3.96) CT34(16.832,-2.97) CT36(16.832,-1.98) CT38(16.832,-0.99) CT40(16.832,0) CT42(16.832,0.99) CT44(16.832,1.98) CT47(16.832,2.97) CT49(16.832,3.96) CT51(16.832,4.95) CT53(16.832,5.941) CT55(16.832,6.931) CT58(16.832,7.921) CT60(16.832,8.911) CT62(16.832,9.901) CT64(16.832,10.891) CT66(16.832,11.881) CT68(16.832,12.871) CT70(16.832,13.861) CU3(17.353,-16.642) CU10(17.327,-13.366) CU13(17.327,-12.376) CU15(17.327,-11.386) CU17(17.327,-10.396) CU19(17.327,-9.406) CU21(17.327,-8.416) CU24(17.327,-7.426) CU26(17.327,-6.436) CU28(17.327,-5.446) CU30(17.327,-4.455) CU32(17.327,-3.465) CU35(17.327,-2.475) CU37(17.327,-1.485) CU39(17.327,-0.495) CU41(17.327,0.495) CU43(17.327,1.485) CU46(17.327,2.475) CU48(17.327,3.465) CU50(17.327,4.455) CU52(17.327,5.446) CU54(17.327,6.436) CU57(17.327,7.426) CU59(17.327,8.416) CU61(17.327,9.406) CU63(17.327,10.396) CU65(17.327,11.386) CU67(17.327,12.376) CU69(17.327,13.366) CU76(17.353,16.642) CV6(18.064,-15.219) CV73(18.064,15.219) D8(-16.337,-14.356) D10(-16.337,-13.366) D13(-16.337,-12.376) D15(-16.337,-11.386) D17(-16.337,-10.396) D19(-16.337,-9.406) D21(-16.337,-8.416) D24(-16.337,-7.426) D26(-16.337,-6.436) D28(-16.337,-5.446) D30(-16.337,-4.455) D32(-16.337,-3.465) D35(-16.337,-2.475) D37(-16.337,-1.485) D39(-16.337,-0.495) D41(-16.337,0.495) D43(-16.337,1.485) D46(-16.337,2.475) D48(-16.337,3.465) D50(-16.337,4.455) D52(-16.337,5.446) D54(-16.337,6.436) D57(-16.337,7.426) D59(-16.337,8.416) D61(-16.337,9.406) D63(-16.337,10.396) D65(-16.337,11.386) D67(-16.337,12.376) D69(-16.337,13.366) D71(-16.337,14.356) E9(-15.842,-13.861) E12(-15.842,-12.871) E14(-15.842,-11.881) E16(-15.842,-10.891) E18(-15.842,-9.901) E20(-15.842,-8.911) E23(-15.842,-7.921) E25(-15.842,-6.931) E27(-15.842,-5.941) E29(-15.842,-4.95) E31(-15.842,-3.96) E34(-15.842,-2.97) E36(-15.842,-1.98) E38(-15.842,-0.99) E40(-15.842,0) E42(-15.842,0.99) E44(-15.842,1.98) E47(-15.842,2.97) E49(-15.842,3.96) E51(-15.842,4.95) E53(-15.842,5.941) E55(-15.842,6.931) E58(-15.842,7.921) E60(-15.842,8.911) E62(-15.842,9.901) E64(-15.842,10.891) E66(-15.842,11.881) E68(-15.842,12.871) E70(-15.842,13.861) F1(-15.219,-18.064) F78(-15.219,18.064) H4(-14.356,-16.337) H75(-14.356,16.337) J3(-13.861,-16.832) J5(-13.861,-15.842) J74(-13.861,15.842) J76(-13.861,16.832) K2(-13.366,-17.327) K4(-13.366,-16.337) K75(-13.366,16.337) K77(-13.366,17.327) L3(-12.871,-16.832) L5(-12.871,-15.842) L74(-12.871,15.842) L76(-12.871,16.832) M2(-12.376,-17.327) M4(-12.376,-16.337) M75(-12.376,16.337) M77(-12.376,17.327) N3(-11.881,-16.832) N5(-11.881,-15.842) N74(-11.881,15.842) N76(-11.881,16.832) R2(-11.386,-17.327) R4(-11.386,-16.337) R75(-11.386,16.337) R77(-11.386,17.327) T3(-10.891,-16.832) T5(-10.891,-15.842) T74(-10.891,15.842) T76(-10.891,16.832) U2(-10.396,-17.327) U4(-10.396,-16.337) U75(-10.396,16.337) U77(-10.396,17.327) V3(-9.901,-16.832) V5(-9.901,-15.842) V74(-9.901,15.842) V76(-9.901,16.832) W2(-9.406,-17.327) W4(-9.406,-16.337) W75(-9.406,16.337) W77(-9.406,17.327) Y3(-8.911,-16.832) Y5(-8.911,-15.842) Y74(-8.911,15.842) Y76(-8.911,16.832)
  oval 0.343x0.254 smd: A9(-18.064,-13.861) A12(-18.064,-12.871) A14(-18.064,-11.881) A16(-18.064,-10.891) A18(-18.064,-9.901) A20(-18.064,-8.911) A23(-18.064,-7.921) A25(-18.064,-6.931) A27(-18.064,-5.941) A29(-18.064,-4.95) A31(-18.064,-3.96) A34(-18.064,-2.97) A36(-18.064,-1.98) A38(-18.064,-0.99) A40(-18.064,0) A42(-18.064,0.99) A44(-18.064,1.98) A47(-18.064,2.97) A49(-18.064,3.96) A51(-18.064,4.95) A53(-18.064,5.941) A55(-18.064,6.931) A58(-18.064,7.921) A60(-18.064,8.911) A62(-18.064,9.901) A64(-18.064,10.891) A66(-18.064,11.881) A68(-18.064,12.871) A70(-18.064,13.861) CV9(18.064,-13.861) CV12(18.064,-12.871) CV14(18.064,-11.881) CV16(18.064,-10.891) CV18(18.064,-9.901) CV20(18.064,-8.911) CV23(18.064,-7.921) CV25(18.064,-6.931) CV27(18.064,-5.941) CV29(18.064,-4.95) CV31(18.064,-3.96) CV34(18.064,-2.97) CV36(18.064,-1.98) CV38(18.064,-0.99) CV40(18.064,0) CV42(18.064,0.99) CV44(18.064,1.98) CV47(18.064,2.97) CV49(18.064,3.961) CV51(18.064,4.951) CV53(18.064,5.941) CV55(18.064,6.931) CV58(18.064,7.921) CV60(18.064,8.911) CV62(18.064,9.901) CV64(18.064,10.891) CV66(18.064,11.881) CV68(18.064,12.871) CV70(18.064,13.862)
  round 0.584 smd: A77(-18.064,17.353) B78(-17.353,18.064) CU1(17.353,-18.064) CU78(17.353,18.064) CV2(18.064,-17.353) CV77(18.064,17.353)
  oval 0.254x0.343 smd: AB1(-7.921,-18.064) AB78(-7.921,18.064) AD1(-6.931,-18.064) AD78(-6.931,18.064) AF1(-5.941,-18.064) AF78(-5.941,18.064) AH1(-4.95,-18.064) AH78(-4.95,18.064) AL1(-3.96,-18.064) AL78(-3.96,18.064) AN1(-2.97,-18.064) AN78(-2.97,18.064) AR1(-1.98,-18.064) AR78(-1.98,18.064) AU1(-0.99,-18.064) AU78(-0.99,18.064) AW1(0,-18.064) AW78(0,18.064) BA1(0.99,-18.064) BA78(0.99,18.064) BD1(1.98,-18.064) BD78(1.98,18.064) BF1(2.97,-18.064) BF78(2.97,18.064) BH1(3.96,-18.064) BH78(3.96,18.064) BK1(4.95,-18.064) BK78(4.95,18.064) BM1(5.941,-18.064) BM78(5.941,18.064) BP1(6.931,-18.064) BP78(6.931,18.064) BT1(7.921,-18.064) BT78(7.921,18.064) BW1(8.911,-18.064) BW78(8.911,18.064) CA1(9.901,-18.064) CA78(9.901,18.064) CC1(10.891,-18.064) CC78(10.891,18.064) CE1(11.881,-18.064) CE78(11.881,18.064) CG1(12.871,-18.064) CG78(12.871,18.064) CJ1(13.861,-18.064) CJ78(13.861,18.064) J1(-13.861,-18.064) J78(-13.861,18.064) L1(-12.871,-18.064) L78(-12.871,18.064) N1(-11.881,-18.064) N78(-11.881,18.064) T1(-10.891,-18.064) T78(-10.891,18.064) V1(-9.901,-18.064) V78(-9.901,18.064) Y1(-8.911,-18.064) Y78(-8.911,18.064)
  round 0.305 smd: B5(-17.353,-15.931) B8(-17.327,-14.54) B71(-17.327,14.54) B74(-17.353,15.931) C3(-16.642,-16.642) C7(-16.832,-15.136) C73(-16.832,15.136) C76(-16.642,16.642) CL2(14.54,-17.327) CL5(14.851,-15.842) CL74(14.851,15.842) CL77(14.54,17.327) CM3(15.136,-16.832) CM76(15.136,16.832) CN4(15.73,-16.337) CN5(15.641,-15.641) CN74(15.641,15.641) CN75(15.73,16.337) CP2(15.931,-17.353) CP7(15.842,-14.851) CP72(15.842,14.851) CP77(15.931,17.353) CR3(16.642,-16.642) CR5(16.337,-15.73) CR74(16.337,15.73) CR76(16.642,16.642) CT7(16.832,-15.136) CT73(16.832,15.136) CU5(17.365,-15.841) CU8(17.327,-14.54) CU71(17.327,14.54) CU74(17.353,15.931) D5(-16.337,-15.73) D74(-16.337,15.73) E2(-15.931,-17.353) E4(-15.73,-16.337) E5(-15.641,-15.641) E7(-15.842,-14.851) E72(-15.842,14.851) E74(-15.641,15.641) E75(-15.73,16.337) E77(-15.931,17.353) F3(-15.136,-16.832) F76(-15.136,16.832) G5(-14.851,-15.842) G74(-14.851,15.842) H2(-14.54,-17.327) H77(-14.54,17.327)
